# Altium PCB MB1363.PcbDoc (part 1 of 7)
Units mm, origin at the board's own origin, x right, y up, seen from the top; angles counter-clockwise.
Board outline 70 x 133.34 mm, 6 copper layers (Top Layer, Signal Layer 1, Signal Layer 2, Signal Layer 3, Signal Layer 4, Bottom Layer), stack 1.57 mm thick; 356 components, 294 nets, 1448 pads, 1107 vias.
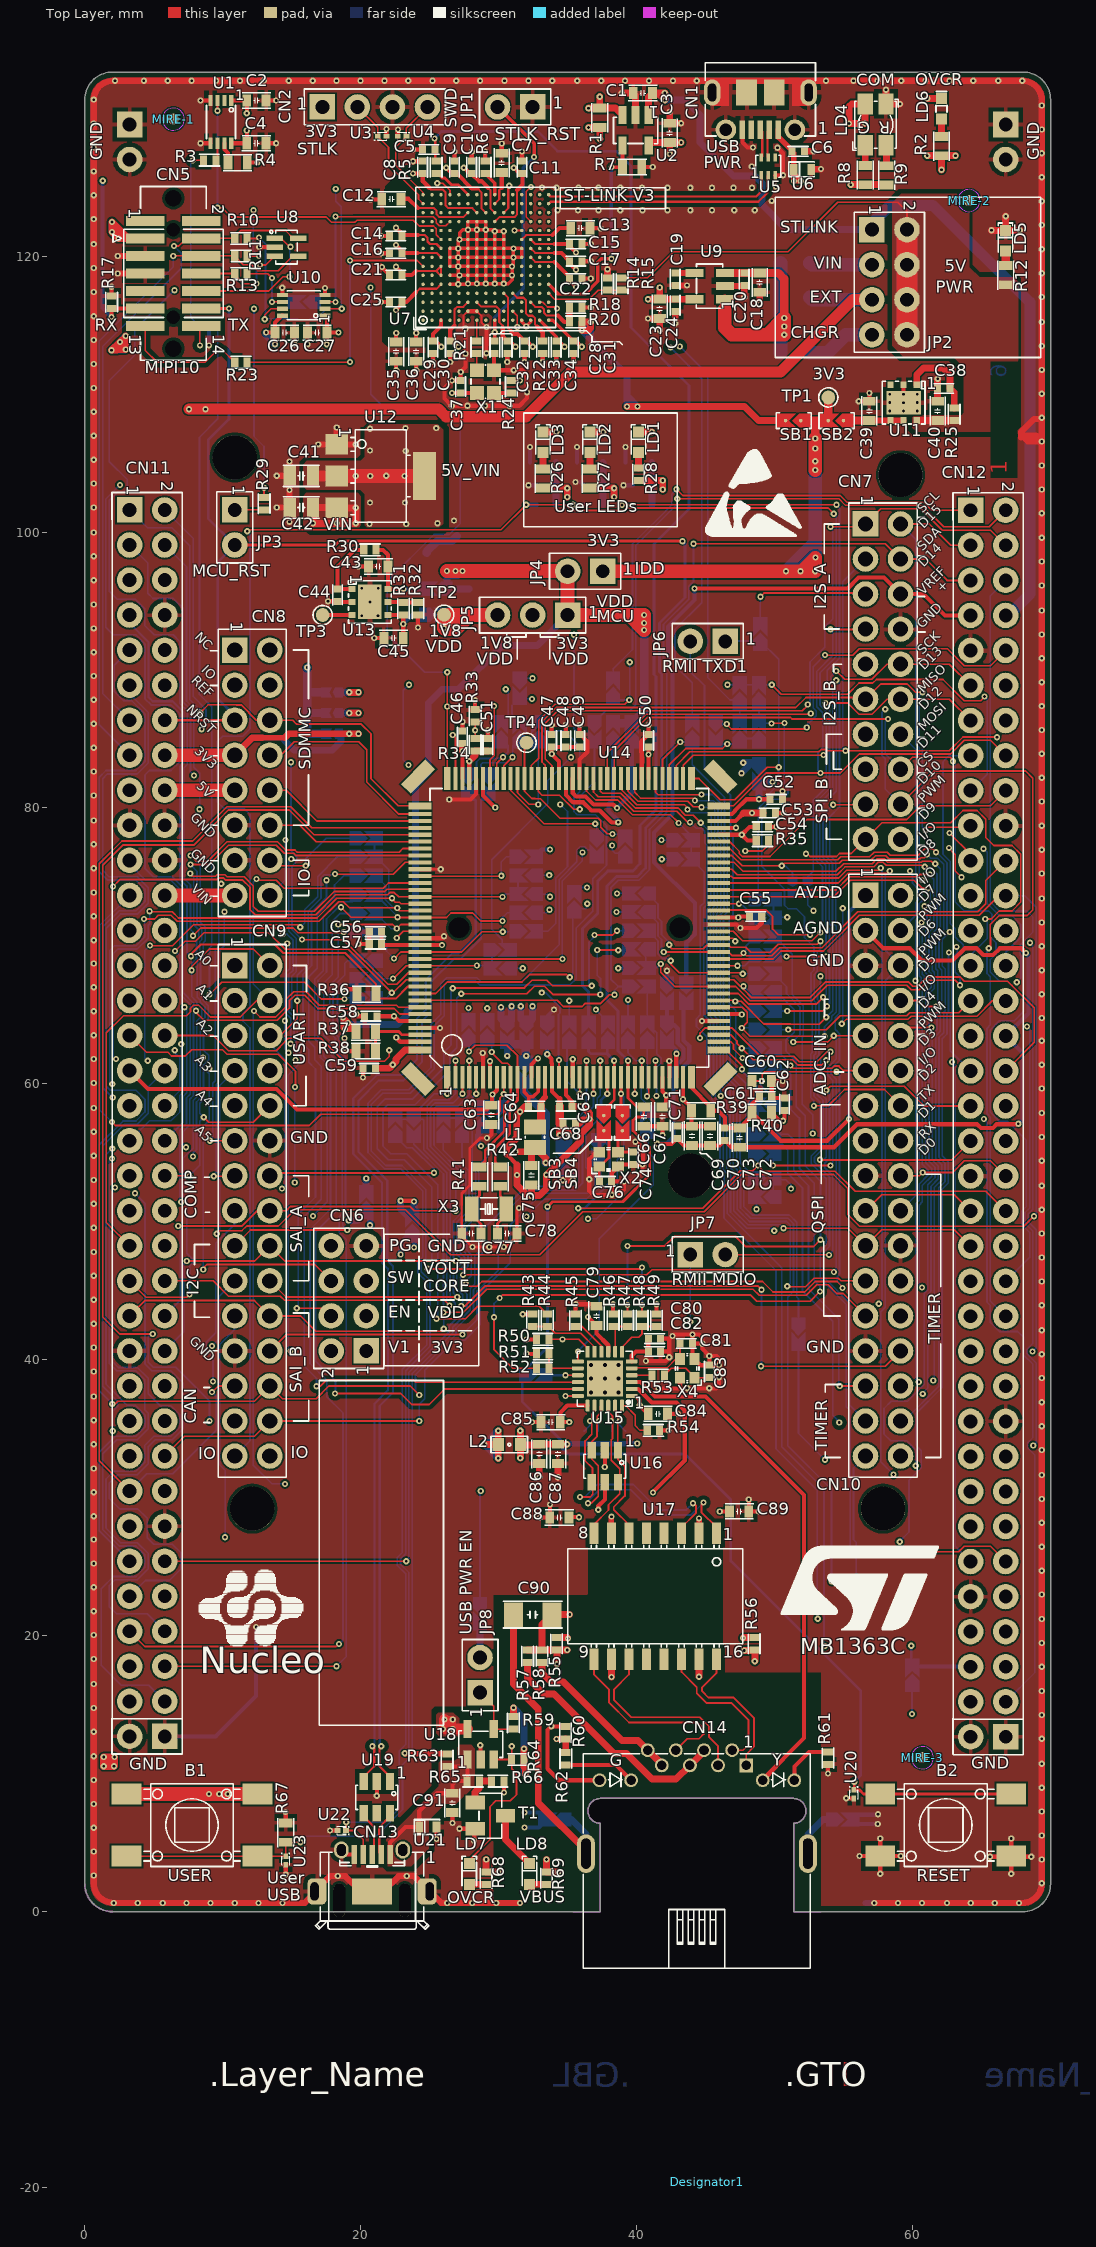
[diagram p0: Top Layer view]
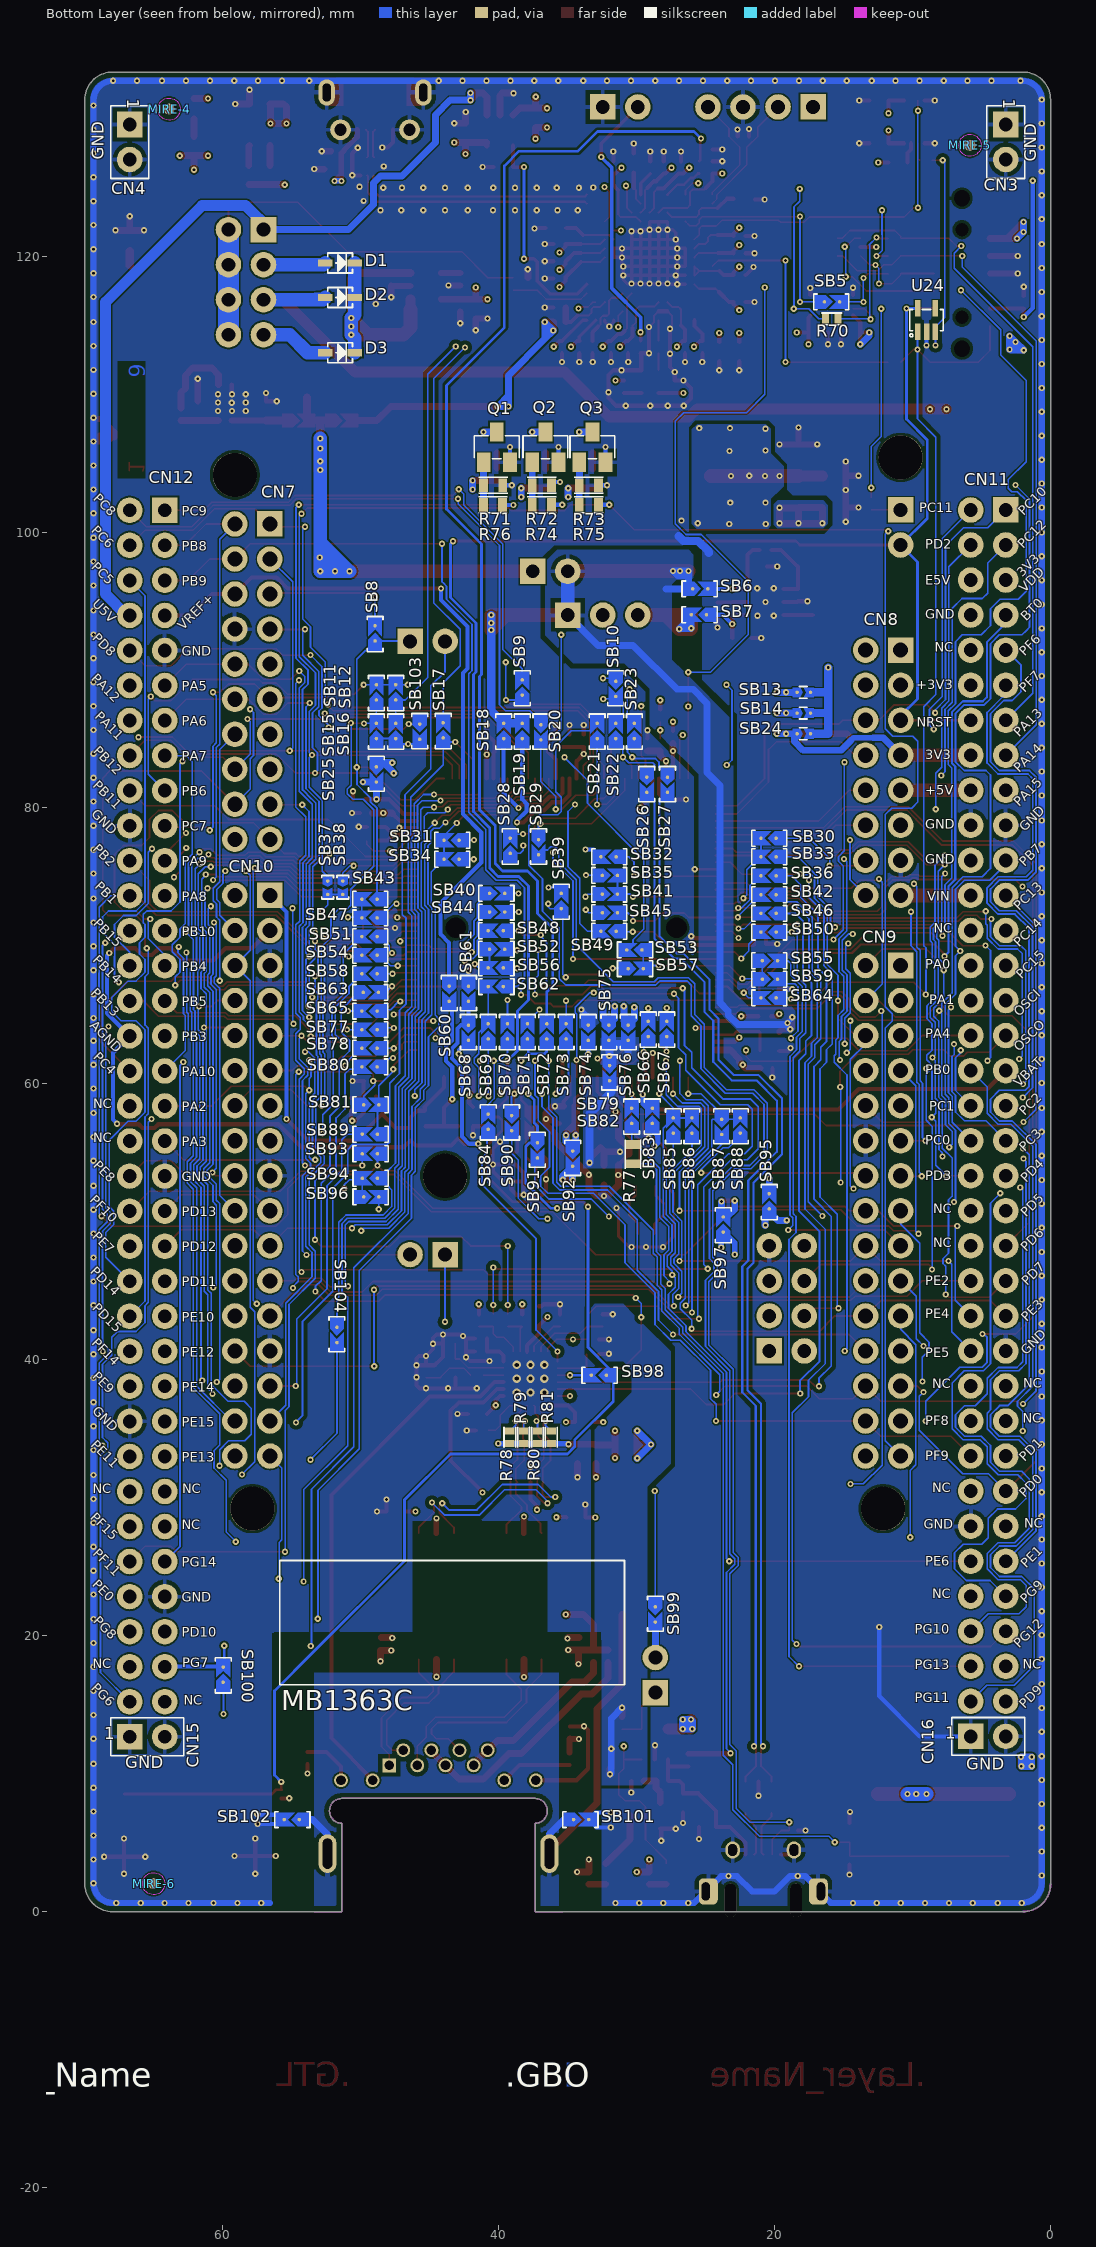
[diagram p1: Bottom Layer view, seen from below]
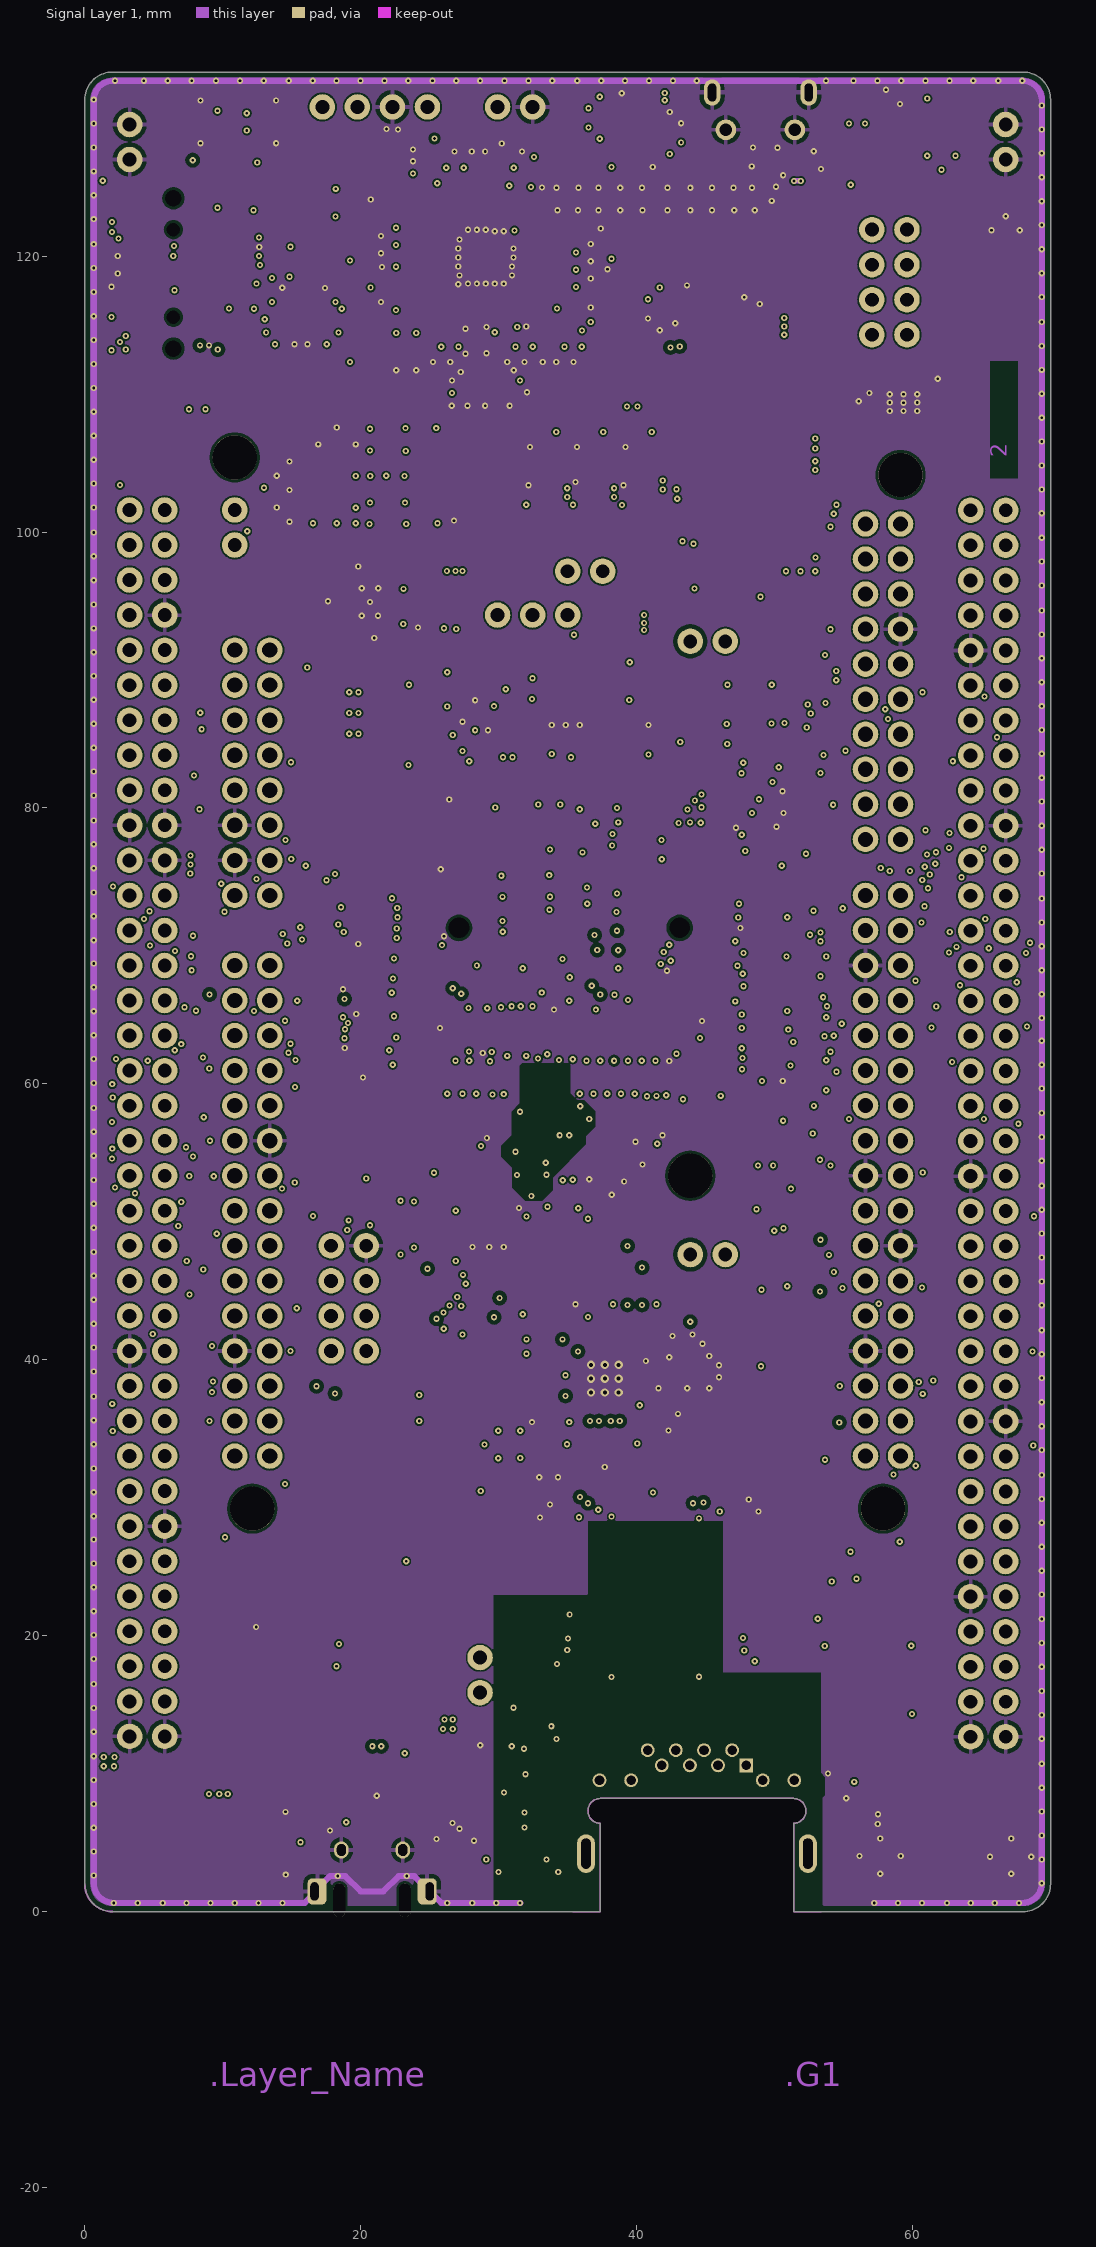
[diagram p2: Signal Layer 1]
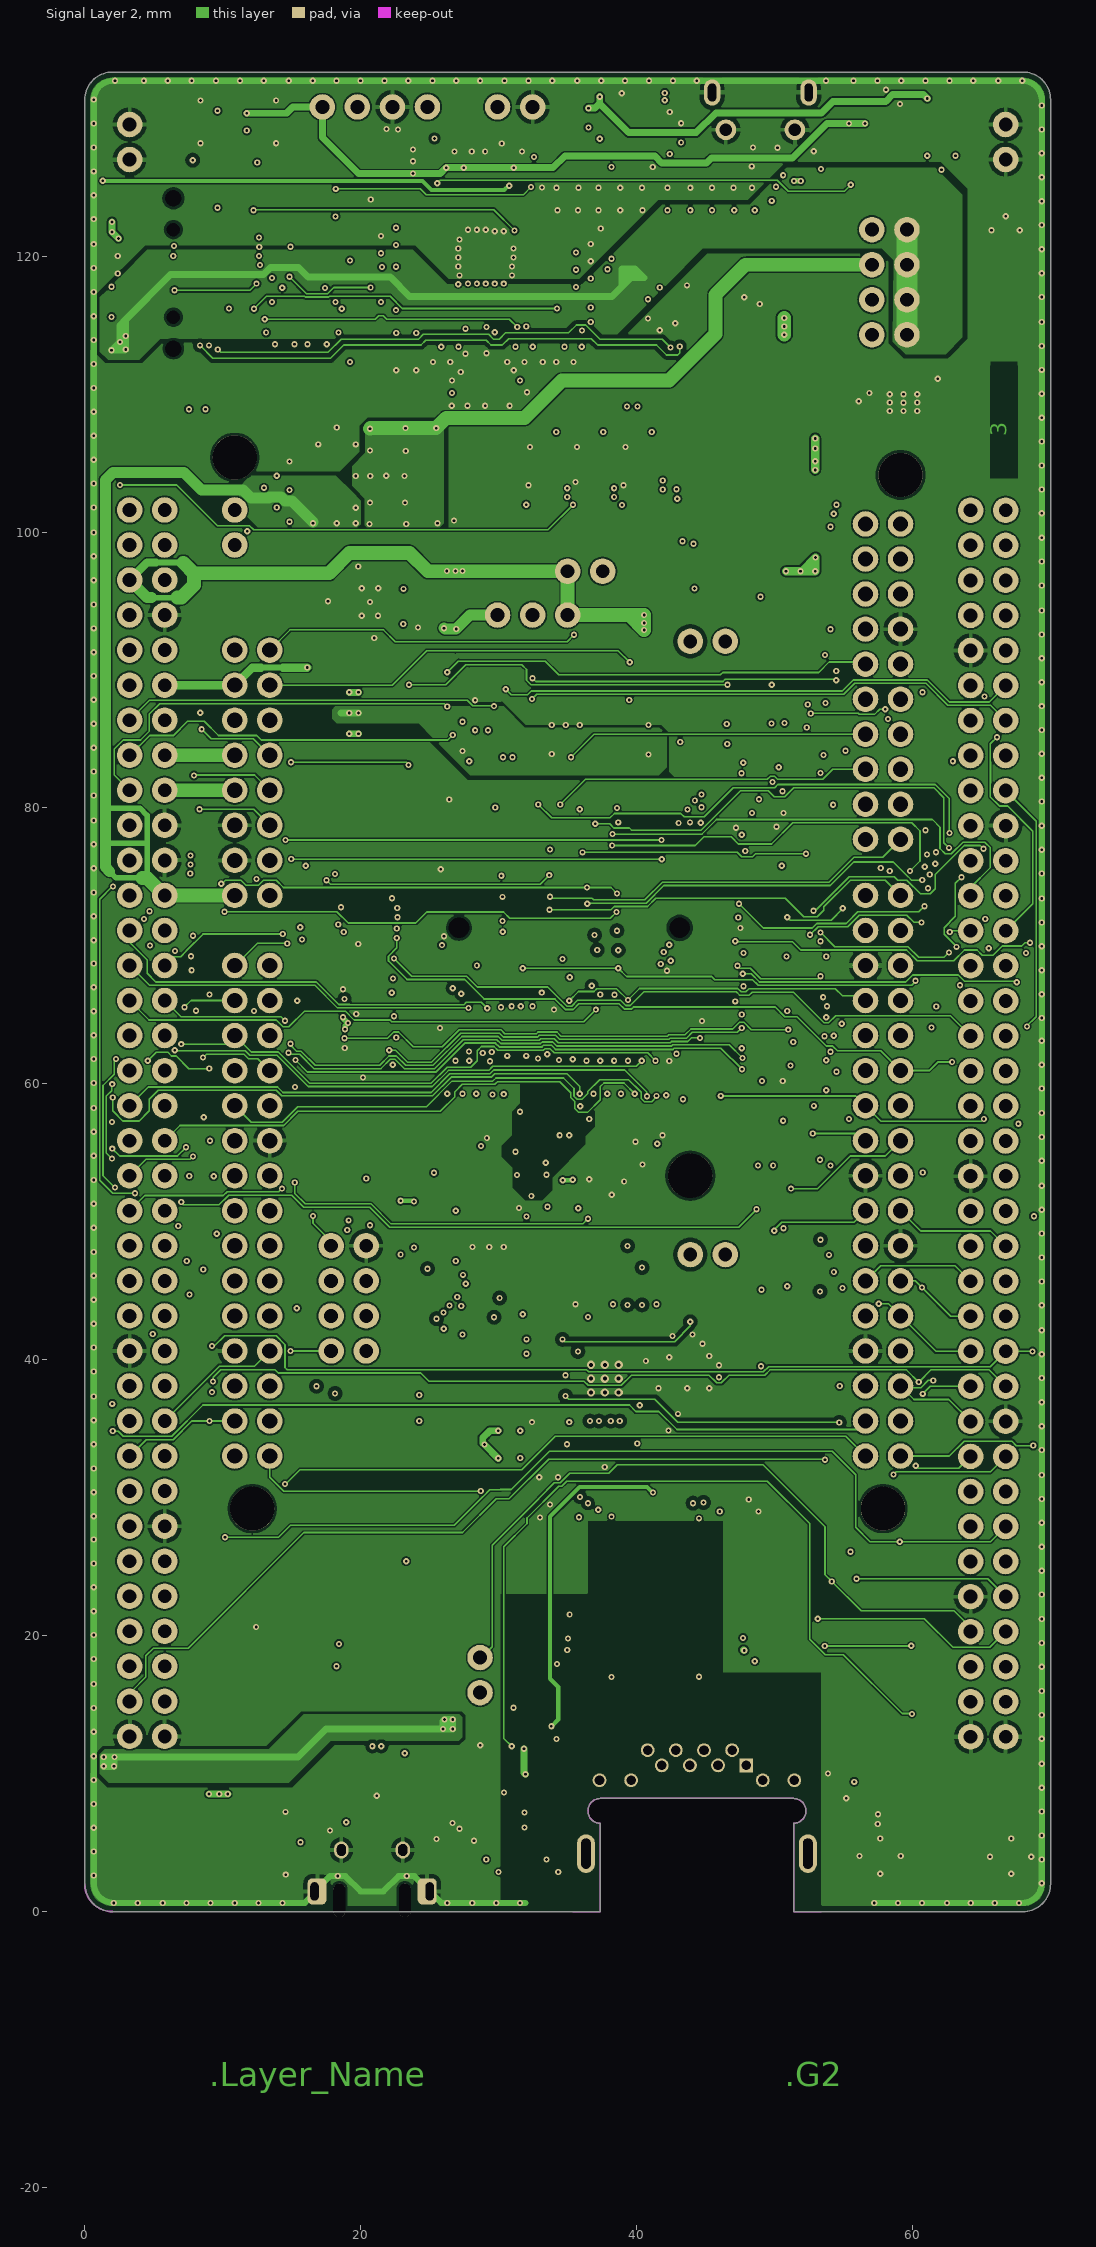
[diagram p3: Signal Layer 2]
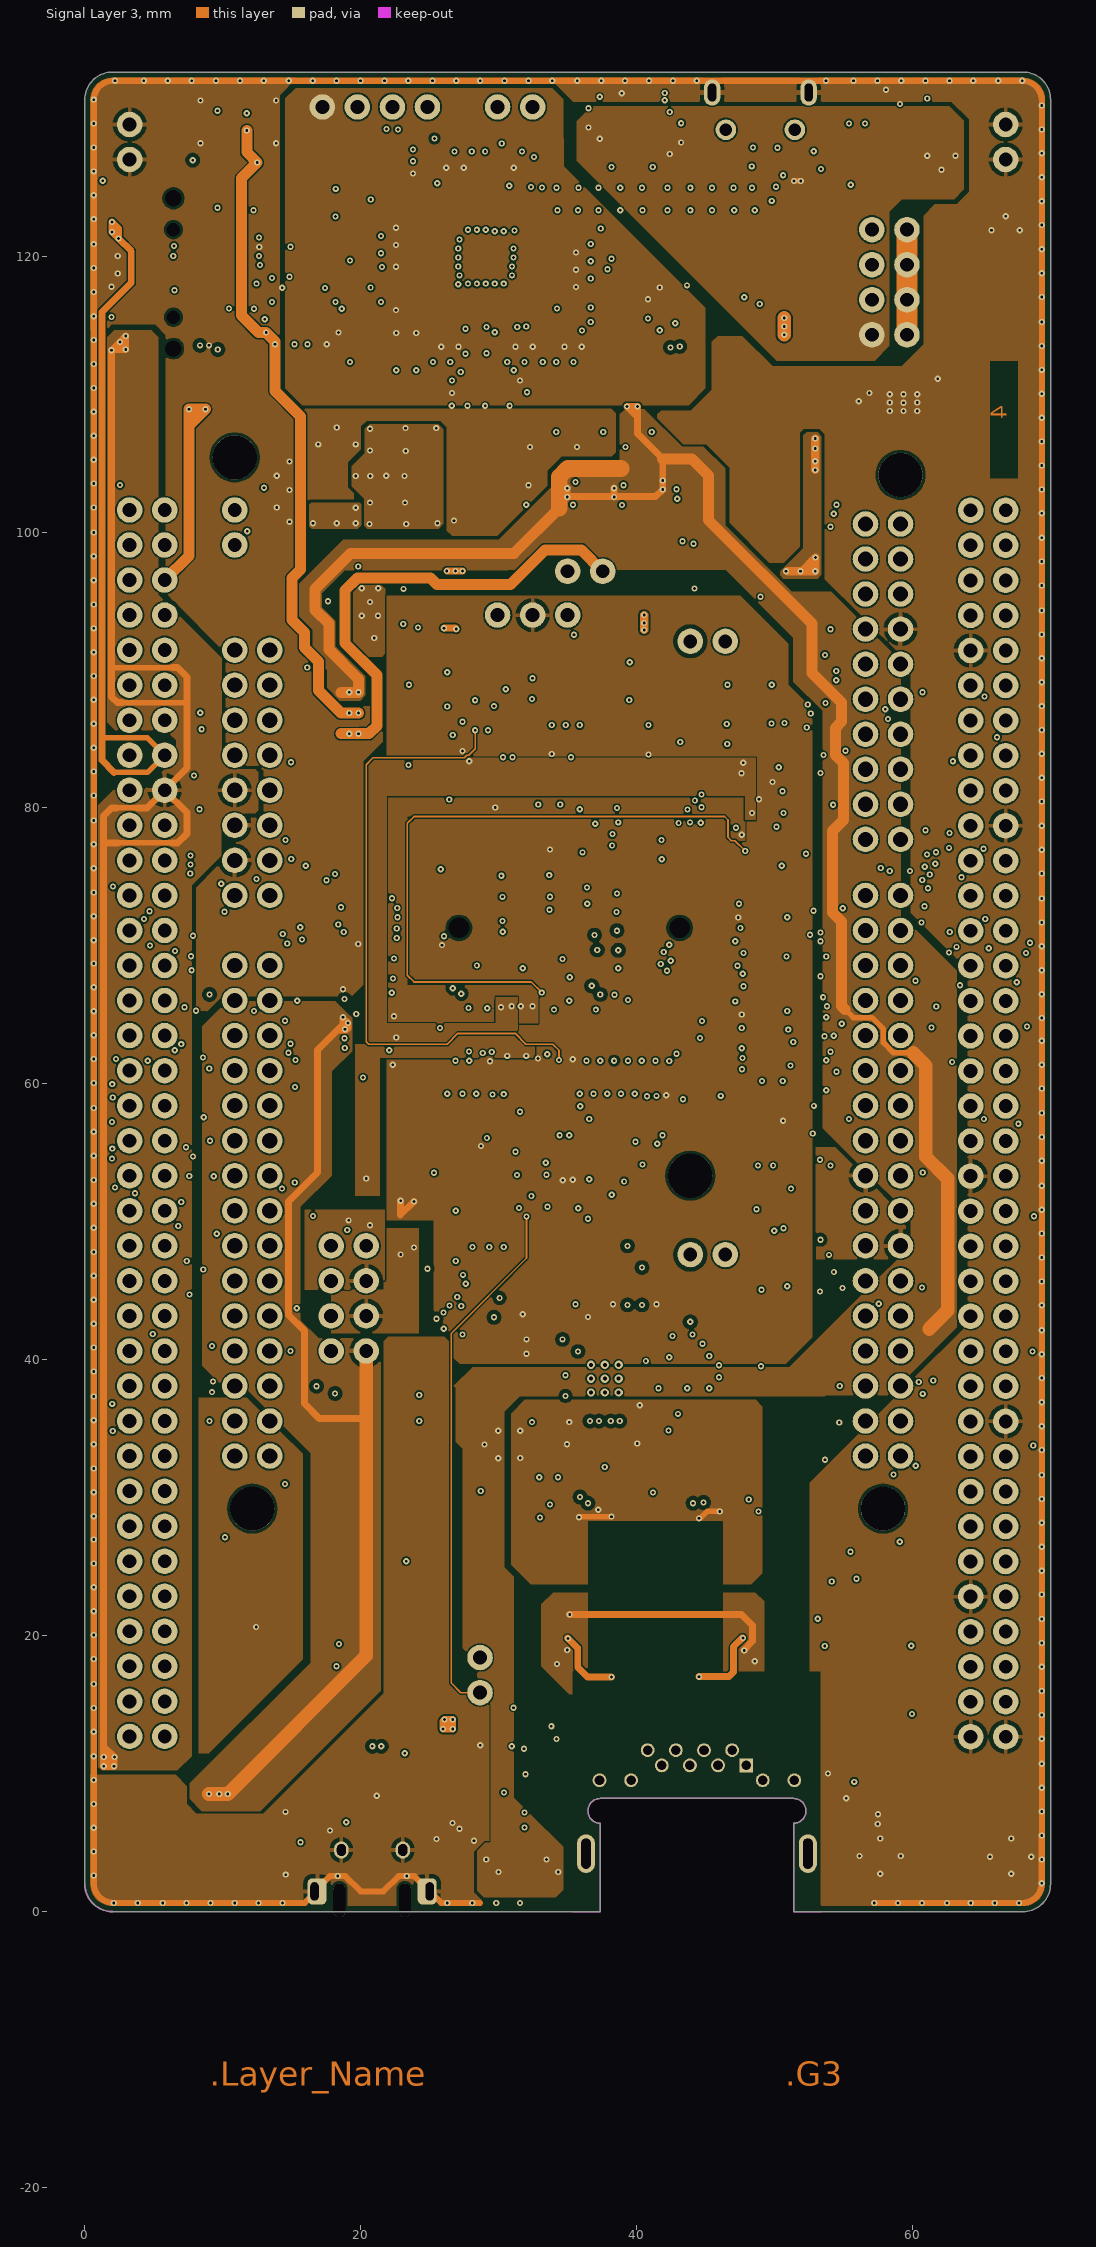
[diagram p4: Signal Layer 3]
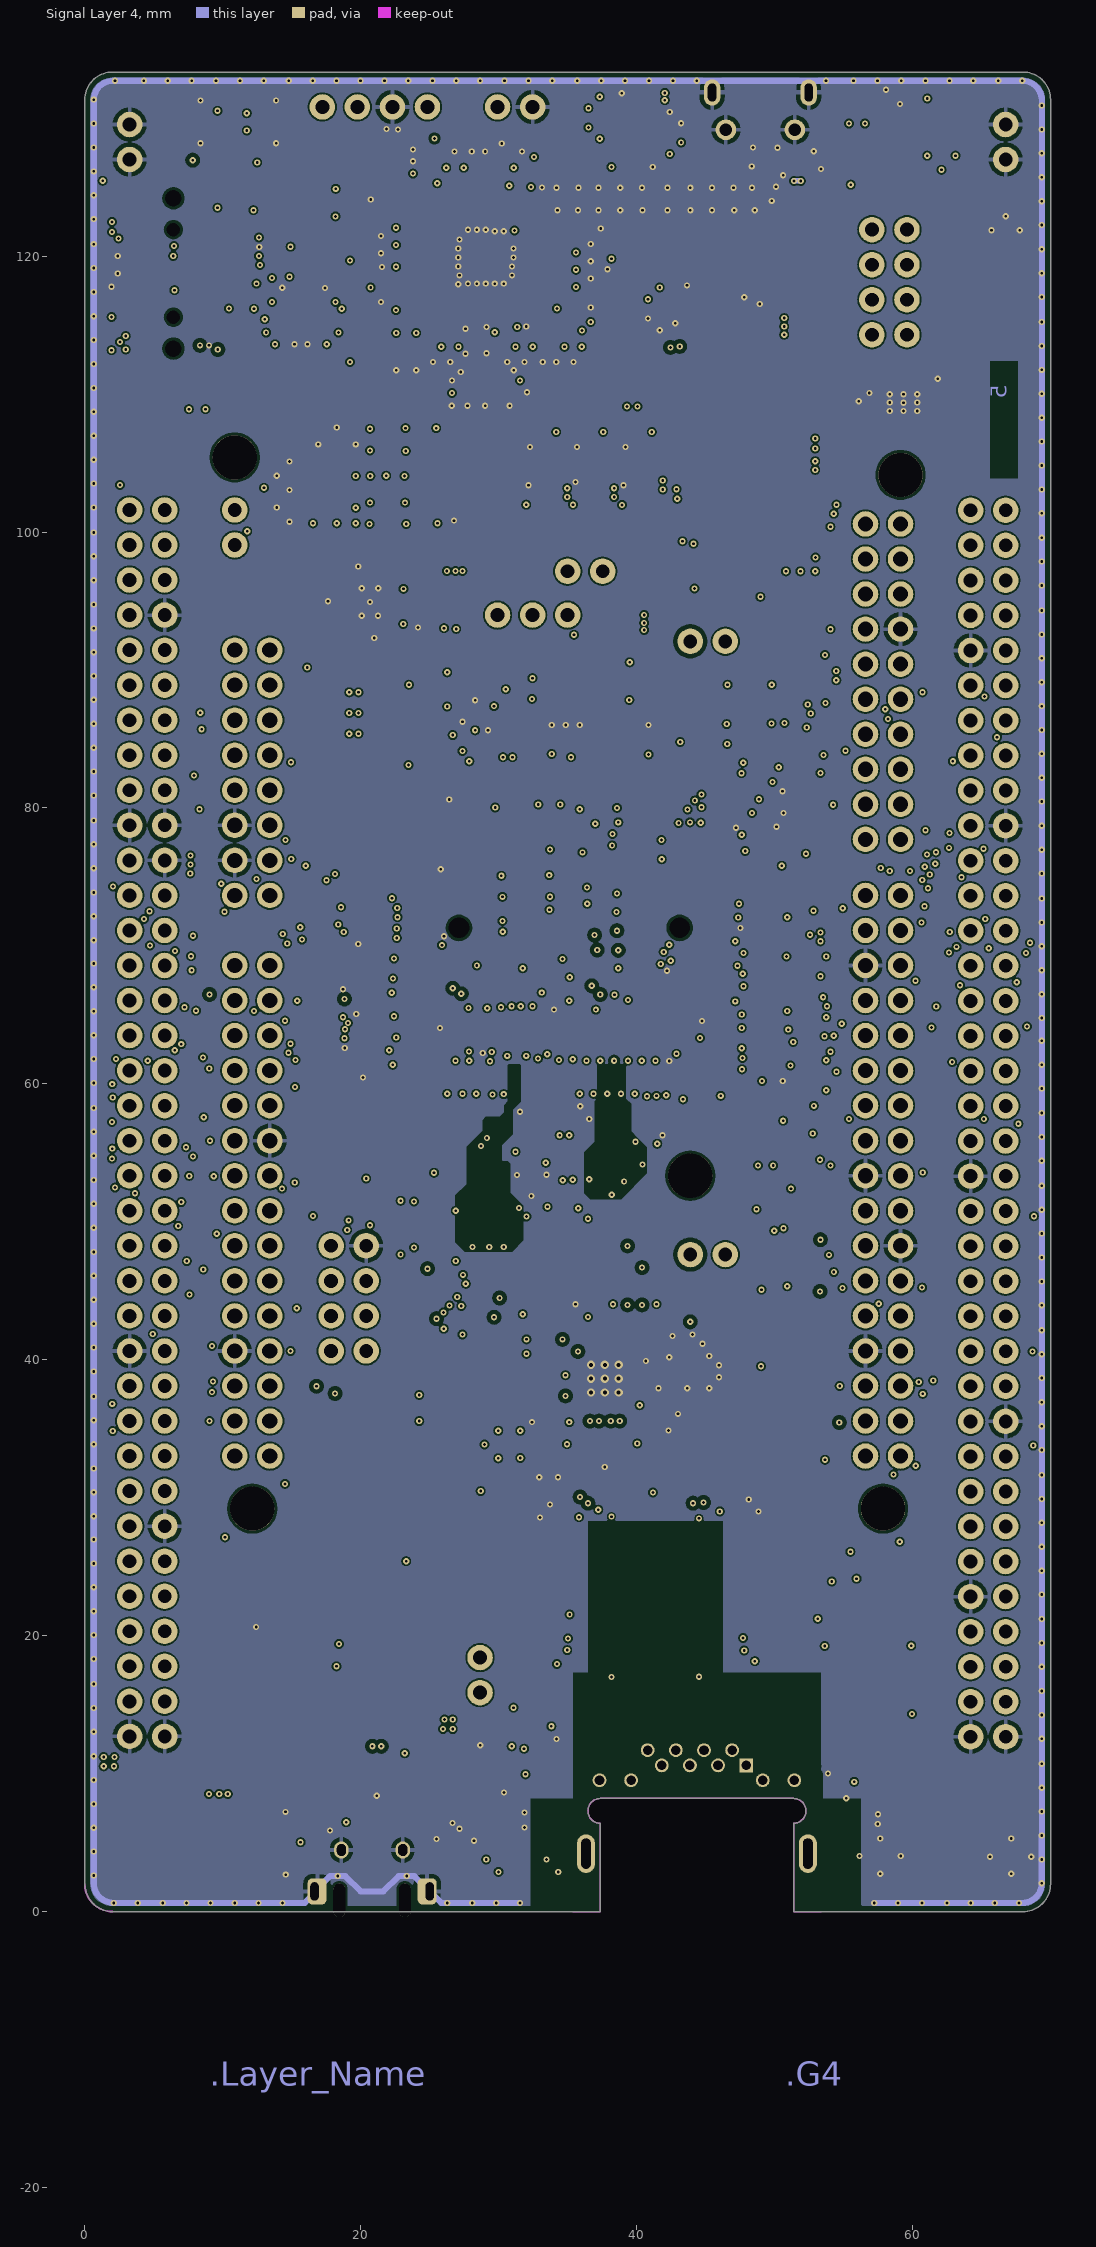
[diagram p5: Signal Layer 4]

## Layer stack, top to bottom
Top Solder: solder mask 0.015, Solder Resist, Dk 3.5
Top Layer: signal copper 0.042
Dielectric 1: prepreg 0.0991, FR-4, Dk 4.2
Signal Layer 1: signal copper 0.0348
Dielectric 2: core 0.1016, Dk 4.2
Signal Layer 2: signal copper 0.0348
Dielectric 3: prepreg 0.9457, Dk 4.2
Signal Layer 3: signal copper 0.0348
Dielectric 4: core 0.1016, Dk 4.2
Signal Layer 4: signal copper 0.0348
Dielectric 5: prepreg 0.0991, Dk 4.2
Bottom Layer: signal copper 0.042
Bottom Solder: solder mask 0.015, Solder Resist, Dk 3.5

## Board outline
0,2 ccw(c2,2) 2,0 37.369,0 37.369,6.4 cw(c37.369,7.3) 36.469,7.3 cw(c37.369,7.3) 37.369,8.2 51.369,8.2 cw(c51.369,7.3) 52.269,7.3 cw(c51.369,7.3) 51.369,6.4 51.369,0 68,0 ccw(c68,2) 70,2 70,131.34 ccw(c68,131.34) 68,133.34 2,133.34 ccw(c2,131.34) 0,131.34

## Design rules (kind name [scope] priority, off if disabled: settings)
BoardOutlineClearance [All] p1: gap=0.4 ignorepadtopadclearanceinfootprint=FALSE
Clearance Clearance_RMII_SINGLE_50R [InNetClass('NC_RMII_SINGLE_50R')] p1: gap=0.12 ignorepadtopadclearanceinfootprint=TRUE except(0.2: Arc-Hole Track-Hole SMDPad-SMDPad SMDPad-THPad SMDPad-Hole THPad-THPad THPad-Hole Via-Via Via-Hole Fill-Hole Poly-Hole Region-Hole Text-Hole; 0.3: Arc-Fill Arc-Poly Track-Track Track-Fill Track-Poly SMDPad-Fill SMDPad-Poly THPad-Fill THPad-Poly Via-Fill Via-Poly Fill-Fill Fill-Poly Poly-Poly)
Clearance Clearance_VCP_ISO300 [InNetClass('NC_VCP_ISO300')] p2: gap=0.12 ignorepadtopadclearanceinfootprint=TRUE except(0.2: Arc-Hole Track-Hole SMDPad-SMDPad SMDPad-THPad SMDPad-Hole THPad-THPad THPad-Hole Via-Via Via-Hole Fill-Hole Poly-Hole Region-Hole Text-Hole; 0.3: Arc-Fill Arc-Poly Track-Track Track-Fill Track-Poly SMDPad-Fill SMDPad-Poly THPad-Fill THPad-Poly Via-Fill Via-Poly Fill-Fill Fill-Poly Poly-Poly)
Clearance Clearance_USB_DIFF_90R [InNetClass('NC_USB_DIFF_90R')] p3: gap=0.12 ignorepadtopadclearanceinfootprint=TRUE except(0.2: Arc-Hole Track-Hole SMDPad-SMDPad SMDPad-THPad SMDPad-Hole THPad-THPad THPad-Hole Via-Via Via-Hole Fill-Hole Poly-Hole Region-Hole Text-Hole; 0.3: Arc-Fill Arc-Poly Track-Fill Track-Poly SMDPad-Fill SMDPad-Poly THPad-Fill THPad-Poly Via-Fill Via-Poly Fill-Fill Fill-Poly Poly-Poly)
Clearance Clearance_RXTX_DIFF_100R [InNetClass('NC_RXTX_DIFF_100R')] p4: gap=0.12 ignorepadtopadclearanceinfootprint=TRUE except(0.2: Arc-Hole Track-Hole SMDPad-SMDPad SMDPad-THPad SMDPad-Hole THPad-THPad THPad-Hole Via-Via Via-Hole Fill-Hole Poly-Hole Region-Hole Text-Hole; 0.3: Arc-Fill Arc-Poly Track-Fill Track-Poly SMDPad-Fill SMDPad-Poly THPad-Fill THPad-Poly Via-Fill Via-Poly Fill-Fill Fill-Poly Poly-Poly)
Clearance Clearance_STLK_ISO200 [InNetClass('NC_STLK_W200-ISO200')] p5: gap=0.12 ignorepadtopadclearanceinfootprint=TRUE except(0.2: Arc-Poly Arc-Hole Track-Track Track-Poly Track-Hole SMDPad-SMDPad SMDPad-THPad SMDPad-Poly SMDPad-Hole THPad-THPad THPad-Poly THPad-Hole Via-Via Via-Poly Via-Hole Fill-Poly Fill-Hole Poly-Poly Poly-Hole Region-Hole Text-Hole; 0.3: Arc-Fill Track-Fill SMDPad-Fill THPad-Fill Via-Fill Fill-Fill)
Clearance [All] p6: gap=0.12 ignorepadtopadclearanceinfootprint=TRUE except(0.2: Arc-Hole Track-Hole SMDPad-SMDPad SMDPad-THPad SMDPad-Hole THPad-THPad THPad-Hole Via-Via Via-Hole Fill-Hole Poly-Hole Region-Hole Text-Hole; 0.3: Arc-Fill Track-Fill SMDPad-Fill THPad-Fill Via-Fill Fill-Fill)
ComponentClearance [All] p1: gap=0 collisioncheckmode=3 verticalgap=0 showdistances=FALSE
DiffPairsRouting DiffPairsRouting_USB_90R [InDifferentialPairClass('DPC_USB_DIFF_90R')] p1: maxlimit=0.252 minlimit=0.226 mostfreqgap=0.226 toplayer_mingap=0.226 toplayer_maxgap=0.226 toplayer_minwidth=0.155 toplayer_maxwidth=0.155 toplayer_prefwidth=0.155 midlayer1_mingap=0.226 midlayer1_maxgap=0.226 midlayer1_minwidth=0.155 midlayer1_maxwidth=0.155 midlayer1_prefwidth=0.155 midlayer2_mingap=0.252 midlayer2_prefgap=0.252 midlayer2_minwidth=0.13 midlayer2_maxwidth=0.13 midlayer2_prefwidth=0.13 midlayer3_maxgap=0.226 midlayer3_prefgap=0.226 midlayer3_minwidth=0.155 midlayer3_maxwidth=0.155 midlayer3_prefwidth=0.155 midlayer4_mingap=0.226 midlayer4_maxgap=0.226 midlayer4_minwidth=0.155 midlayer4_maxwidth=0.155 midlayer4_prefwidth=0.155 bottomlayer_mingap=0.226 bottomlayer_maxgap=0.226 bottomlayer_minwidth=0.155 bottomlayer_maxwidth=0.155 bottomlayer_prefwidth=0.155 maxuncoupledlength=12.7
DiffPairsRouting DiffPairsRouting_RXTX_100R [InDifferentialPairClass('DPC_RXTX_DIFF_100R')] p2: maxlimit=0.277 minlimit=0.252 mostfreqgap=0.277 toplayer_maxgap=0.252 toplayer_prefgap=0.252 toplayer_minwidth=0.11 toplayer_maxwidth=0.13 toplayer_prefwidth=0.13 midlayer1_maxgap=0.252 midlayer1_prefgap=0.252 midlayer1_minwidth=0.13 midlayer1_maxwidth=0.13 midlayer1_prefwidth=0.13 midlayer2_mingap=0.277 midlayer2_minwidth=0.104 midlayer2_maxwidth=0.104 midlayer2_prefwidth=0.104 midlayer3_maxgap=0.252 midlayer3_prefgap=0.252 midlayer3_minwidth=0.13 midlayer3_maxwidth=0.13 midlayer3_prefwidth=0.13 midlayer4_maxgap=0.252 midlayer4_prefgap=0.252 midlayer4_minwidth=0.13 midlayer4_maxwidth=0.13 midlayer4_prefwidth=0.13 bottomlayer_maxgap=0.252 bottomlayer_prefgap=0.252 bottomlayer_minwidth=0.11 bottomlayer_maxwidth=0.13 bottomlayer_prefwidth=0.13 maxuncoupledlength=12.7
FabricationTestPointUsage TestPointUsage [All] p1: valid=0 allowmultiple=FALSE
FabricationTestpoint Testpoint [(IsPad And (OnTopLayer Or OnBottomLayer))] p1: side=3 testpointundercomponent=TRUE minsize=1.016 maxsize=2.54 preferedsize=1.524 minholesize=0 maxholesize=1.016 preferedholesize=0.813 testpointgrid=0.025 allowsidetop=TRUE allowsidebottom=TRUE usegrid=TRUE gridtolerance=0
HoleSize [All] p1: absolutevalues=TRUE maxlimit=3.81 minlimit=0.025 maxpercent=80.000 minpercent=20.000
MaxMinImpedance "Schematic Impedance Constraint_3" [InNet('USB_DEV_HS_P')] p1: minimum=85,00 maximum=95,00
MaxMinImpedance "Schematic Impedance Constraint_2" [InNet('USB_DEV_HS_N')] p2: minimum=85,00 maximum=95,00
MaxMinImpedance "Schematic Impedance Constraint_1" [InNet('USB_DEV_HS_CN_P')] p3: minimum=85,00 maximum=95,00
MaxMinImpedance "Schematic Impedance Constraint" [InNet('USB_DEV_HS_CN_N')] p4: minimum=85,00 maximum=95,00
MinimumSolderMaskSliver [All] p1: minsoldermaskwidth=0
PolygonConnect PolygonConnect_10 [All vs IsNamedPolygon('USB_FS_VBUS_L01_P068')] p1: connectstyle=Direct reliefconductorwidth=0.254 reliefentries=4 polygonreliefangle="90 Angle" airgapwidth=0.254
PolygonConnect PolygonConnect_9 [All vs IsNamedPolygon('5V_L03_P060')] p2: connectstyle=Direct reliefconductorwidth=0.254 reliefentries=4 polygonreliefangle="90 Angle" airgapwidth=0.254
PolygonConnect PolygonConnect_8 [All vs IsNamedPolygon('5V_L01_P058')] p3: connectstyle=Direct reliefconductorwidth=0.254 reliefentries=4 polygonreliefangle="90 Angle" airgapwidth=0.254
PolygonConnect PolygonConnect_7 [All vs IsNamedPolygon('3V3_STLK_L04_P044')] p4: connectstyle=Direct reliefconductorwidth=0.254 reliefentries=4 polygonreliefangle="90 Angle" airgapwidth=0.254
PolygonConnect PolygonConnect_6 [All vs IsNamedPolygon('5V_USB_CHGR_L04_P042')] p5: connectstyle=Direct reliefconductorwidth=0.254 reliefentries=4 polygonreliefangle="90 Angle" airgapwidth=0.254
PolygonConnect PolygonConnect_5 [All vs IsNamedPolygon('5V_L01_P038')] p6: connectstyle=Direct reliefconductorwidth=0.254 reliefentries=4 polygonreliefangle="90 Angle" airgapwidth=0.254
PolygonConnect PolygonConnect_4 [All vs IsNamedPolygon('5V_L01_P038')] p7: thpad.connectstyle=Relief thpad.reliefconductorwidth=0.4 thpad.reliefentries=4 thpad.polygonreliefangle="90 Angle" thpad.airgapwidth=0.4 smdpad.connectstyle=Direct smdpad.reliefconductorwidth=0.254 smdpad.reliefentries=4 smdpad.polygonreliefangle="90 Angle" smdpad.airgapwidth=0.254 via.connectstyle=Direct via.reliefconductorwidth=0.254 via.reliefentries=4 via.polygonreliefangle="90 Angle" via.airgapwidth=0.254
PolygonConnect PolygonConnect_3 [All vs IsNamedPolygon('5V_VIN_L01_P028')] p8: connectstyle=Direct reliefconductorwidth=0.254 reliefentries=4 polygonreliefangle="90 Angle" airgapwidth=0.254
PolygonConnect PolygonConnect_2 [All vs IsNamedPolygon('VIN_L01_P026')] p9: connectstyle=Direct reliefconductorwidth=0.254 reliefentries=4 polygonreliefangle="90 Angle" airgapwidth=0.254
PolygonConnect PolygonConnect_1 [All vs IsNamedPolygon('GND_L01_P024')] p10: connectstyle=Direct reliefconductorwidth=0.254 reliefentries=4 polygonreliefangle="90 Angle" airgapwidth=0.254
PolygonConnect [All] p11: thpad.connectstyle=Relief thpad.reliefconductorwidth=0.3 thpad.reliefentries=4 thpad.polygonreliefangle="90 Angle" thpad.airgapwidth=0.3 smdpad.connectstyle=Relief smdpad.reliefconductorwidth=0.3 smdpad.reliefentries=4 smdpad.polygonreliefangle="90 Angle" smdpad.airgapwidth=0.3 via.connectstyle=Direct via.reliefconductorwidth=0.254 via.reliefentries=4 via.polygonreliefangle="90 Angle" via.airgapwidth=0.254
RoutingLayers RoutingLayers_USB_DIFF_90R [InDifferentialPairClass('DPC_USB_DIFF_90R')] p1: top layer_v5=TRUE mid layer 1_v5=TRUE mid layer 2_v5=TRUE mid layer 3_v5=TRUE mid layer 4_v5=TRUE bottom layer_v5=TRUE
RoutingLayers RoutingLayers_RXTX_DIFF_100R [InDifferentialPairClass('DPC_RXTX_DIFF_100R')] p2: top layer_v5=TRUE mid layer 1_v5=TRUE mid layer 2_v5=TRUE mid layer 3_v5=TRUE mid layer 4_v5=TRUE bottom layer_v5=TRUE
RoutingLayers RoutingLayers_RMII_SINGLE_50R [InNetClass('NC_RMII_SINGLE_50R')] p3: top layer_v5=TRUE mid layer 1_v5=TRUE mid layer 2_v5=TRUE mid layer 3_v5=TRUE mid layer 4_v5=TRUE bottom layer_v5=TRUE
RoutingVias RoutingVias_Default [All] p1: holewidth=0.2 width=0.45 viastyle="Through Hole" minholewidth=0.2 minwidth=0.45 maxholewidth=0.2 maxwidth=0.45
SilkToSilkClearance [All] p1: silktosilkclearance=0.102
SilkToSolderMaskClearance SilkscreenOverComponentPads [IsPad] p1: minsilkscreentomaskgap=0.102 clearancetoexposedcopper=TRUE
SolderMaskExpansion [All] p1: expansion=0.102
Width Width_RMII_SINGLE_50R [InNetClass('NC_RMII_SINGLE_50R')] p1: maxlimit=0.127 minlimit=0.102 preferedwidth=0.127 toplayer_minwidth=0.127 midlayer1_minwidth=0.127 midlayer2_maxwidth=0.102 midlayer2_prefwidth=0.102 midlayer3_minwidth=0.127 midlayer4_minwidth=0.127 bottomlayer_minwidth=0.127 minimp=50.000000 maximp=50.000000 favimp=50.000000
Width Width_POWER_300u [InNetClass('NC_POWER_300u')] p2: maxlimit=10 minlimit=0.12 preferedwidth=0.3 minimp=50.000000 maximp=50.000000 favimp=50.000000
Width Width_GROUND [InNetClass('NC_GROUND')] p3: maxlimit=10 minlimit=0.12 preferedwidth=0.3 minimp=50.000000 maximp=50.000000 favimp=50.000000
Width Width_POWER_500u [InNetClass('NC_POWER_500u')] p4: maxlimit=10 minlimit=0.12 preferedwidth=0.5 minimp=50.000000 maximp=50.000000 favimp=50.000000
Width Width_POWER_SMPS [InNetClass('NC_POWER_SMPS')] p5: maxlimit=10 minlimit=0.12 preferedwidth=0.5 minimp=50.000000 maximp=50.000000 favimp=50.000000
Width Width_STLK_W200 [InNetClass('NC_STLK_W200-ISO200')] p6: maxlimit=10 minlimit=0.2 preferedwidth=0.2 minimp=50.000000 maximp=50.000000 favimp=50.000000
Width [All] p7: maxlimit=10 minlimit=0.12 preferedwidth=0.12 minimp=50.000000 maximp=50.000000 favimp=50.000000
Width Width_RD_N [InNet('RD_N')] p8: maxlimit=10 minlimit=0.11 preferedwidth=0.12 toplayer_maxwidth=0.11 toplayer_prefwidth=0.11 midlayer1_minwidth=0.12 midlayer2_minwidth=0.12 midlayer3_minwidth=0.12 midlayer4_minwidth=0.12 bottomlayer_maxwidth=0.11 bottomlayer_prefwidth=0.11 minimp=50.000000 maximp=50.000000 favimp=50.000000
Width Width_TD_P [InNet('TD_P')] p9: maxlimit=10 minlimit=0.11 preferedwidth=0.12 toplayer_maxwidth=0.11 toplayer_prefwidth=0.11 midlayer1_minwidth=0.12 midlayer2_minwidth=0.12 midlayer3_minwidth=0.12 midlayer4_minwidth=0.12 bottomlayer_maxwidth=0.11 bottomlayer_prefwidth=0.11 minimp=50.000000 maximp=50.000000 favimp=50.000000
21 further rules are at their usual default settings.

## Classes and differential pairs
net class NC_STLK_W200-ISO200: NetR5_1 PH0 STLK_MCO
net class NC_VCP_ISO300: T_VCP_RX T_VCP_TX
net class NC_RMII_SINGLE_50R: RMII_CRS_DV RMII_MDC RMII_MDIO RMII_REF_CLK RMII_RXD0 RMII_RXD1 RMII_TX_EN RMII_TXD0 RMII_TXD1
net class NC_USB_DIFF_90R: USB_DEV_HS_CN_N USB_DEV_HS_CN_P USB_DEV_HS_N USB_DEV_HS_P USB_FS_CN_N USB_FS_CN_P USB_FS_N USB_FS_P
differential pair class DPC_RXTX_DIFF_100R: RD RX TD TX
differential pair class DPC_USB_DIFF_90R: USB_DEV_HS USB_DEV_HS_CN USB_FS USB_FS_CN
net class NC_RXTX_DIFF_100R: RD_N RD_P RX_N RX_P TD_N TD_P TX_N TX_P
net class NC_GROUND: AGND GND
net class NC_POWER_300u: VBAT VDDA VREFP
net class NC_POWER_SMPS: 1V2_MCU 1V2_VOUTCORE VCAP VDD_LDO VDD_MCU VDD_SMPS_IN VDD_SMPS_IND_OUT VDD_SMPS_OUT VOUTVDD
net class NC_POWER_500u: 1V8_VDD 3V3 3V3_PER 3V3_STLK 3V3_VDD 5V 5V_EXT 5V_USB_CHGR 5V_USB_STLK 5V_VIN IOREF USB_FS_VBUS VIN
differential pair USB_FS_CN: +USB_FS_CN_P -USB_FS_CN_N
differential pair RD: +RD_P -RD_N
differential pair RX: +RX_P -RX_N
differential pair TD: +TD_P -TD_N
differential pair TX: +TX_P -TX_N
differential pair USB_DEV_HS_CN: +USB_DEV_HS_CN_P -USB_DEV_HS_CN_N
differential pair USB_DEV_HS: +USB_DEV_HS_P -USB_DEV_HS_N
differential pair USB_FS: +USB_FS_P -USB_FS_N

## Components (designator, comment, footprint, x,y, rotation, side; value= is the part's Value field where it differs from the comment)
B1 "SW-PUSH-CMS_BLUE" SWI_WEALTHMETAL_TD-0341_4P_BLUE 7.767,6.273 r270 top locked value=SW_BLUE
B2 "SW-PUSH-CMS_BLACK" SWI_WEALTHMETAL_TD-0341_4P_BLACK 62.403,6.273 r270 top locked value=SW_BLACK
C1 "Capacitor" C0603 40.448,131.82 r0 top value=1uF
C2 "Capacitor" C0603 12.441,131.279 r180 top value=100nF
C3 "Capacitor" C0603 42.396,128.927 r270 top value=1uF
C4 "Capacitor" C0603 12.441,128.179 r0 top value=100nF
C5 "Capacitor" C0402 24.941,127.729 r0 top value=20pF
C6 "Capacitor" C0402 51.699,127.593 r180 top value=100pF
C7 "Capacitor" C0603 30.216,126.754 r270 top value=2.2uF
C8 "Capacitor" C0402 24.491,126.429 r270 top value=100nF
C9 "Capacitor" C0402 26.791,126.429 r270 top value=100nF
C10 "Capacitor" C0402 28.041,126.429 r270 top value=100nF
C11 "Capacitor" C0402 31.691,126.429 r270 top value=100nF
C12 "Capacitor" C0603 22.225,124.125 r0 top value=2.2uF
C13 "Capacitor" C0603 35.925,122.025 r180 top value=2.2uF
C14 "Capacitor" C0402 22.541,121.454 r0 top value=100nF
C15 "Capacitor" C0402 35.591,120.879 r180 top value=100nF
C16 "Capacitor" C0402 22.541,120.204 r0 top value=100nF
C17 "Capacitor" C0402 35.591,119.629 r180 top value=100nF
C18 "Capacitor" C0603 48.916,118.079 r270 top value=1uF
C19 "Capacitor" C0402 42.791,118.329 r90 top value=10nF
C20 "Capacitor" C0402 47.794,118.32 r90 top value=100nF
C21 "Capacitor" C0402 22.541,118.629 r0 top value=100nF
C22 "Capacitor" C0402 35.591,118.379 r180 top value=100nF
C23 "Capacitor" C0603 41.666,116.179 r90 top value=1uF
C24 "Capacitor" C0402 42.791,116.429 r90 top value=100nF
C25 "Capacitor" C0402 22.541,116.679 r0 top value=100nF
C26 "Capacitor" C0603 14.491,114.454 r0 top value=100nF
C27 "Capacitor" C0603 16.841,114.454 r0 top value=100nF
C28 "Capacitor" C0402 29.716,113.404 r90 top value=100nF
C29 "Capacitor" C0402 25.241,113.404 r90 top value=100nF
C30 "Capacitor" C0402 26.491,113.404 r90 top value=100nF
C31 "Capacitor" C0402 30.616,113.404 r90 top value=100nF
C32 "Capacitor" C0402 31.866,113.404 r90 top value=100nF
C33 "Capacitor" C0402 34.166,113.404 r90 top value=100nF
C34 "Capacitor" C0402 35.416,113.404 r90 top value=100nF
C35 "Capacitor" C0603 22.566,113.079 r90 top value=4.7uF
C36 "Capacitor" C0603 24.016,113.079 r90 top value=1uF
C37 "Capacitor" C0402 27.241,110.529 r270 top value=100nF
C38 "Capacitor" C0402 62.266,110.404 r180 top value=100nF
C39 "Capacitor" C0603 56.866,108.779 r270 top value=4.7uF
C40 "Capacitor" C0603 61.816,108.779 r270 top value=4.7uF
C41 "Capacitor" C0805 15.691,104.074 r0 top value=10uF
C42 "Capacitor" C0805 15.691,101.774 r0 top value=10uF
C43 "Capacitor" C0603 21.266,97.504 r180 top value=4.7uF
C44 "Capacitor" C0402 18.316,95.429 r270 top value=100nF
C45 "Capacitor" C0603 22.375,92.325 r0 top value=4.7uF
C46 "Capacitor" C0402 27.366,85.129 r270 top value=100nF
C47 "Capacitor" C0402 33.839,84.879 r270 top value=100nF
C48 "Capacitor" C0402 34.866,84.879 r270 top value=100nF
C49 "Capacitor" C0402 35.866,84.879 r270 top value=100nF
C50 "Capacitor" C0402 40.866,84.879 r270 top value=100nF
C51 "Capacitor" C0402 29.216,84.579 r90 top value=100nF
C52 "Capacitor" C0402 50.116,80.629 r180 top value=100nF
C53 "Capacitor" C0402 49.616,79.629 r0 top value=100nF
C54 "Capacitor" C0402 49.116,78.629 r180 top value=100nF
C55 "Capacitor" C0402 48.616,72.129 r180 top value=100nF
C56 "Capacitor" C0402 21.066,71.029 r0 top value=100nF
C57 "Capacitor" C0402 21.066,70.129 r0 top value=100nF
C58 "Capacitor" C0402 20.716,64.904 r0 top value=100nF
C59 "Capacitor" C0402 20.616,61.129 r0 top value=100nF
C60 "Capacitor" C0603 49.066,60.204 r180 top value=100nF
C61 "Capacitor" C0402 49.341,59.079 r0 top value=100nF
C62 "Capacitor" C0402 50.716,58.529 r90 top value=100nF
C63 "Capacitor" C0603 29.466,57.754 r90 top value=1uF
C64 "Capacitor" C0402 32.616,58.379 r0 top value=220pF
C65 "Capacitor" C0402 34.866,58.379 r180 top value=10uF
C66 "Capacitor" C0603 40.516,57.629 r90 top value=100nF
C67 "Capacitor" C0603 41.866,57.629 r90 top value=4.7uF
C68 "Capacitor" C0402 35.116,57.129 r180 top value=10uF
C69 "Capacitor" C0603 44.016,56.229 r270 top value=1uF
C70 "Capacitor" C0603 45.316,56.229 r90 top value=100nF
C71 "Capacitor" C0402 42.941,56.479 r90 top value=100nF
C72 "Capacitor" C0603 47.466,56.104 r270 top value=1uF
C73 "Capacitor" C0402 46.391,56.354 r90 top value=100nF
C74 "Capacitor" C0402 39.766,54.604 r270 top value=5.6pF
C75 "Capacitor" C0603 32.366,53.379 r90 top value=10uF
C76 "Capacitor" C0402 37.741,52.929 r0 top value=5.6pF
C77 "Capacitor" C0603 28.016,49.154 r180 top value=5.1pF
C78 "Capacitor" C0603 30.616,49.154 r0 top value=5.1pF
C79 "Capacitor" C0603 37.091,43.179 r270 top value=100nF
C80 "Capacitor" C0402 41.291,41.529 r180 top value=1uF
C81 "Capacitor" C0402 43.591,41.179 r180 top value=5.6pF
C82 "Capacitor" C0402 41.291,40.604 r180 top value=470pF
C83 "Capacitor" C0402 45.266,39.154 r270 top value=5.6pF
C84 "Capacitor" C0603 41.541,36.079 r180 top value=100nF
C85 "Capacitor" C0603 33.766,35.479 r180 top value=100nF
C86 "Capacitor" C0603 32.941,33.179 r90 top value=100nF
C87 "Capacitor" C0603 34.291,33.179 r90 top value=10uF
C88 "Capacitor" C0603 34.396,28.566 r0 top value=100nF
C89 "Capacitor" C0603 47.429,29.009 r180 top value=100nF
C90 "Capacitor" C1206_H1P6 32.466,21.529 r0 top value=1nF
C91 "Capacitor" C0603 26.641,7.879 r90 top value=4.7uF
CN1 "USB_uB_105017.0001" CON_USBMICROB_MOLEX_105017-0001_H2P90 48.966,133.308 r180 top locked value=USB_uB_105017-0001
CN2 "Header 4x1" CON_SAMTEC_TSW-104-07-G-S 21.026,130.809 r0 top
CN3 "Jumper_Header 2x1" CON_SAMTEC_TSW-102-09-X-S 3.246,128.269 r270 bottom locked value="Header 2x1 16mm"
CN4 "Jumper_Header 2x1" CON_SAMTEC_TSW-102-09-X-S 66.746,128.269 r270 bottom locked value="Header 2x1 16mm"
CN5 "Header 7x2" CON_STDC14_Receiver_MEDIUM_WITH_MIPI10_3D 6.421,118.744 r270 top value="MIPI10 on STDC14 footprint"
CN6 "Jumper_Header 4x2" CON_SAMTEC_TSW-104-07-X-D 19.121,44.449 r90 top value=Jumper_Header_4x2
CN7 "Socket 10x2_N144_ARD" CON_SAMTEC_SSW-110-23-X-D_N144_ARD 57.856,89.153 r90 top locked
CN8 "Socket 8x2_N144_ARD" CON_SAMTEC_SSW-108-23-X-D_N144_ARD 12.136,82.549 r90 top locked
CN9 "Socket 15x2_N144_ARD" CON_SAMTEC_SSW-115-23-X-D_N144_ARD 12.136,50.799 r90 top locked
CN10 "Socket 17x2_N144_ARD" CON_SAMTEC_SSW-117-23-X-D_N144_ARD 57.856,53.339 r90 top locked
CN11 "Header 35x2" CON_SAMTEC_TSW-135-07-X-D 4.516,58.419 r270 top locked
CN12 "Header 35x2" CON_SAMTEC_TSW-135-07-X-D 65.476,58.394 r270 top locked
CN13 "USB_uAB_47590.0001" CON_USBMICROAB_MOLEX_47590-0001_H3 20.823,0.014 r0 top locked value="USB uAB ZX62RD-AB-5P8(30)"
CN14 "RJ45_KRJ-CB4.2GYZNL" CON_RJ45_DGKYD_KRJ-CB4.2GYZNL 44.369,0 r0 top locked value=KRJ-CB4.2GYZNL
CN15 "Jumper_Header 2x1" CON_SAMTEC_TSW-102-09-X-S 65.476,12.674 r180 bottom locked value="Header 2x1 16mm"
CN16 "Jumper_Header 2x1" CON_SAMTEC_TSW-102-09-X-S 4.516,12.699 r180 bottom value="Header 2x1 16mm"
D1 "BAT60JFILM" DIO_SOD323 51.5,119.5 r180 bottom
D2 "BAT60JFILM" DIO_SOD323 51.5,117 r180 bottom
D3 "BAT60JFILM" DIO_SOD323 51.5,113 r180 bottom
Designator1 "Comment" Sheetbox_6L2S 0.04,-24.86 r0 top
JP1 "Jumper_Header 2x1" CON_SAMTEC_TSW-102-07-G-S 31.186,130.809 r180 top value="Shunt not fitted"
JP2 "Jumper_Header 4x2 Fitted 1-2" CON_SAMTEC_TSW-104-07-X-D 58.32,118.109 r270 top locked value="Shunt Fitted 1-2"
JP3 "Jumper_Header 2x1 Fitted" CON_SAMTEC_TSW-102-07-G-S 10.866,100.329 r270 top value="Shunt Fitted"
JP4 "Jumper_Header 2x1 Fitted" CON_SAMTEC_TSW-102-07-G-S 36.266,97.154 r180 top value="Shunt Fitted"
JP5 "Jumper_Header 3x1 Fitted 1-2" CON_SAMTEC_TSW-103-07-F-S 32.456,93.979 r180 top value="Shunt Fitted 1-2"
JP6 "Jumper_Header 2x1 Fitted" CON_SAMTEC_TSW-102-07-G-S 45.156,92.074 r180 top value="Shunt Fitted"
JP7 "Jumper_Header 2x1 Fitted" CON_SAMTEC_TSW-102-07-G-S 45.156,47.624 r0 top value="Shunt Fitted"
JP8 "Jumper_Header 2x1 Fitted" CON_SAMTEC_TSW-102-07-G-S 28.646,17.144 r90 top value="Shunt Fitted"
L1 "Inductor" L0805_H0P9 32.616,56.129 r270 top value="2.2uH, 1.2A"
L2 "BEAD" L0603 30.766,33.854 r180 top value=600R@100MHz
LD1 "LED_green" LED_0603_OSRAM_LG-Q396-PS-35_GREEN_1A2K_H0P4 40.141,106.497 r90 top locked value=GREEN
LD2 "LED_yellow" LED_0603_OSRAM_LY-Q396-P1Q2-36_YELLOW_1A2K_H0P4 36.616,106.497 r90 top value=YELLOW
LD3 "LED_red" LED_0603_OSRAM_LS-Q976-NR-1_RED_1A2K_H0P8 33.208,106.497 r90 top value=RED
LD4 "LD_BICOLOR_CMS" LED_BI-GR_HSMF-A201-A00J1 57.316,129.529 r180 top
LD5 "LED_green" LED_0603_OSRAM_LG-Q396-PS-35_GREEN_1A2K_H0P4 66.746,121.119 r90 top value=GREEN
LD6 "LED_red" LED_0603_RED 62.091,130.679 r90 top value=RED
LD7 "LED_red" LED_0603_VISHAY_VLMS1300-GS08_RED_1A2K_H0P8 27.866,2.729 r90 top value=RED
LD8 "LED_green" LED_0603_OSRAM_LG-Q396-PS-35_GREEN_1A2K_H0P4 32.241,2.729 r90 top value=GREEN
MIRE-1 "Comment" MIRE_PLACE_SMD_0P8MM 6.416,129.929 r0 top
MIRE-2 "Comment" MIRE_PLACE_SMD_0P8MM 64.091,124.029 r0 top
MIRE-3 "Comment" MIRE_PLACE_SMD_0P8MM 60.716,11.154 r0 top
MIRE-4 "Comment" MIRE_PLACE_SMD_0P8MM 63.891,130.654 r180 bottom
MIRE-5 "Comment" MIRE_PLACE_SMD_0P8MM 5.841,128.029 r180 bottom
MIRE-6 "Comment" MIRE_PLACE_SMD_0P8MM 65.016,2.029 r180 bottom
Q1 "9013-SOT23" NPN_SOT23 40.141,106.147 r180 bottom
Q2 "9013-SOT23" NPN_SOT23 36.616,106.147 r180 bottom
Q3 "9013-SOT23" NPN_SOT23 33.208,106.147 r180 bottom
R1 "Resistor" R0603 37.325,130.029 r270 top value=100K
R2 "Resistor" R0603 62.091,127.979 r270 top value=1K
R3 "Resistor" R0402 9.041,126.954 r0 top value=47R
R4 "Resistor" R0603 11.066,126.779 r0 top value=100K
R5 "Resistor" R0402 25.466,126.429 r90 top value=100R
R6 "Resistor" R0402 29.016,126.429 r270 top value=3K
R7 "Resistor" R0603 39.673,126.459 r0 top value=10K
R8 "Resistor" R0603 56.566,125.877 r270 top value=330R
R9 "Resistor" R0603 58.116,125.852 r270 top value=330R
R10 "Resistor" R0402 11.316,121.279 r0 top value=47R
R11 "Resistor" R0402 11.316,120.004 r180 top value=47R
R12 "Resistor" R0603 66.746,118.619 r270 top value=620R
R13 "Resistor" R0402 11.316,118.729 r0 top value=47R
R14 "Resistor" R0402 37.891,117.979 r270 top value=4K7
R15 "Resistor" R0402 38.941,117.979 r270 top value=2K7
R17 "Resistor" R0402 1.941,116.654 r270 top value=100R
R18 "Resistor" R0402 35.591,116.279 r0 top value=4K7
R20 "Resistor" R0402 35.591,115.229 r0 top value=4K7
R21 "Resistor" R0402 28.416,113.404 r90 top value=100R
R22 "Resistor" R0402 33.191,113.404 r90 top value=10K
R23 "Resistor" R0402 11.316,112.304 r180 top value=47R
R24 "Resistor" R0402 30.916,110.529 r270 top value=10K
R25 "Resistor" R0402 63.016,108.529 r270 top value=10K
R26 "Resistor" R0603 33.216,103.879 r270 top value=360R
R27 "Resistor" R0603 36.616,103.879 r270 top value=470R
R28 "Resistor" R0402 40.141,104.179 r270 top value=270R
R29 "Resistor" R0402 12.991,102.054 r270 top value=47R
R30 "Resistor" R0402 20.666,98.704 r180 top value=10K
R31 "Resistor" R0402 23.1,94.45 r90 top value=27K
R32 "Resistor" R0402 24.15,94.45 r90 top value=56K
R33 "Resistor" R0402 28.291,86.679 r90 top value=0R
R34 "Resistor" R0402 28.291,84.579 r90 top value=0R
R35 "Resistor" R0402 49.116,77.629 r0 top value=0R
R36 "Resistor" R0603 20.416,66.504 r180 top value=10K
R37 "Resistor" R0603 20.366,63.753 r180 top value=10K
R38 "Resistor" R0603 20.366,62.379 r180 top value=10K
R39 "Resistor" R0603 44.666,58.054 r180 top value=0R
R40 "Resistor" R0603 49.066,57.929 r180 top value=0R
R41 "Resistor" R0603 28.616,53.279 r270 top value=0R
R42 "Resistor" R0603 30.116,53.279 r270 top value=0R
R43 "Resistor" R0402 32.466,42.854 r90 top value=10K
R44 "Resistor" R0402 33.516,42.854 r270 top value=33R
R45 "Resistor" R0402 35.566,42.854 r90 top value=10K
R46 "Resistor" R0402 38.291,42.854 r90 top value=10K
R47 "Resistor" R0402 39.341,42.854 r270 top value=33R
R48 "Resistor" R0402 40.391,42.854 r270 top value=33R
R49 "Resistor" R0402 41.441,42.854 r90 top value=10K
R50 "Resistor" R0402 33.191,41.479 r180 top value=1K5
R51 "Resistor" R0402 33.191,40.429 r180 top value=10K
R52 "Resistor" R0402 33.191,39.379 r0 top value=33R
R53 "Resistor" R0402 41.566,38.879 r180 top value=0R
R54 "Resistor" R0402 41.216,34.879 r0 top value=12K1
R55 "Resistor" R0402 34.191,19.404 r90 top value=75R
R56 "Resistor" R0402 48.516,19.404 r90 top value=75R
R57 "Resistor" R0402 32.091,18.504 r270 top value=75R
R58 "Resistor" R0402 33.141,18.504 r270 top value=75R
R59 "Resistor" R0402 31.066,13.679 r90 top value=47K
R60 "Resistor" R0402 34.841,12.973 r90 top value=10K
R61 "Resistor" R0402 53.866,11.129 r90 top value=270R
R62 "Resistor" R0402 34.866,11.079 r270 top value=270R
R63 "Resistor" R0402 26.266,10.979 r90 top value=10K
R64 "Resistor" R0402 31.391,11.024 r0 top value=47K
R65 "Resistor" R0402 28.141,9.454 r0 top value=47K
R66 "Resistor" R0402 29.941,9.454 r180 top value=10K
R67 "Resistor" R0603 14.566,5.729 r270 top value=100K
R68 "Resistor" R0402 29.091,2.429 r90 top value=360R
R69 "Resistor" R0402 33.466,2.429 r90 top value=270R
R70 "Resistor" R0402 15.866,115.454 r0 bottom value=100R
R71 "Resistor" R0603 40.411,103.385 r0 bottom value=100K
R72 "Resistor" R0603 36.866,103.379 r0 bottom value=100K
R73 "Resistor" R0603 33.466,103.379 r0 bottom value=100K
R74 "Resistor" R0603 36.866,101.979 r0 bottom value=47K
R75 "Resistor" R0603 33.466,101.979 r0 bottom value=47K
R76 "Resistor" R0603 40.414,101.967 r0 bottom value=47K
R77 "Resistor" R0603 30.266,54.904 r270 bottom value=330R
R78 "Resistor" R0402 39.191,34.379 r270 bottom value=49.9R
R79 "Resistor" R0402 38.191,34.379 r270 bottom value=49.9R
R80 "Resistor" R0402 37.191,34.379 r270 bottom value=49.9R
R81 "Resistor" R0402 36.191,34.379 r270 bottom value=49.9R
SB1 "SB_ON" SOLDER-BRIDGE_R0603-0R 51.391,108.079 r180 top
SB2 "SB_ON" SOLDER-BRIDGE_R0603-0R 54.491,108.079 r180 top
SB3 "SB_ON" SOLDER-BRIDGE_R0603-0R 37.616,57.204 r270 top
SB4 "SB_ON" SOLDER-BRIDGE_R0603-0R 38.966,57.204 r270 top
SB5 "SB_ON" SOLDER-BRIDGE_R0603-0R 15.891,116.679 r180 bottom
SB6 "SB_ON" SOLDER-BRIDGE_R0603-0R 25.441,95.879 r180 bottom
SB7 "SB_ON" SOLDER-BRIDGE_R0603-0R 25.441,94.004 r0 bottom
SB8 "SB_ON" SOLDER-BRIDGE_R0603-0R 48.966,92.604 r90 bottom
SB9 "SB_ON" SOLDER-BRIDGE_R0603-0R 38.291,88.679 r90 bottom
SB10 "SB_ON" SOLDER-BRIDGE_R0603-0R 31.516,88.679 r270 bottom
SB11 "SB_ON" SOLDER-BRIDGE_R0603-0R 48.866,88.329 r90 bottom
SB12 "SB_ON" SOLDER-BRIDGE_R0603-0R 47.466,88.329 r90 bottom
SB13 "SB_ON" SOLDER-BRIDGE_R0402-0R 17.925,88.375 r180 bottom
SB14 "SB_ON" SOLDER-BRIDGE_R0402-0R 17.925,86.875 r180 bottom
SB15 "SB_ON" SOLDER-BRIDGE_R0603-0R 48.866,85.529 r90 bottom
SB16 "SB_ON" SOLDER-BRIDGE_R0603-0R 47.466,85.529 r90 bottom
SB17 "SB_ON" SOLDER-BRIDGE_R0603-0R 44.025,85.575 r90 bottom
SB18 "SB_ON" SOLDER-BRIDGE_R0603-0R 39.641,85.529 r90 bottom
SB19 "SB_ON" SOLDER-BRIDGE_R0603-0R 38.291,85.529 r90 bottom
SB20 "SB_ON" SOLDER-BRIDGE_R0603-0R 36.941,85.529 r270 bottom
SB21 "SB_ON" SOLDER-BRIDGE_R0603-0R 32.866,85.529 r90 bottom
SB22 "SB_ON" SOLDER-BRIDGE_R0603-0R 31.516,85.529 r90 bottom
SB23 "SB_ON" SOLDER-BRIDGE_R0603-0R 30.166,85.529 r90 bottom
SB24 "SB_ON" SOLDER-BRIDGE_R0402-0R 17.925,85.375 r180 bottom
SB25 "SB_ON" SOLDER-BRIDGE_R0603-0R 48.866,82.479 r270 bottom
SB26 "SB_ON" SOLDER-BRIDGE_R0603-0R 29.266,81.729 r270 bottom
SB27 "SB_ON" SOLDER-BRIDGE_R0603-0R 27.766,81.729 r270 bottom
SB28 "SB_ON" SOLDER-BRIDGE_R0603-0R 39.166,77.204 r90 bottom
SB29 "SB_ON" SOLDER-BRIDGE_R0603-0R 37.116,77.204 r270 bottom
SB30 "SB_ON" SOLDER-BRIDGE_R0603-0R 20.391,77.804 r0 bottom
SB31 "SB_ON" SOLDER-BRIDGE_R0603-0R 43.366,77.654 r0 bottom
SB32 "SB_ON" SOLDER-BRIDGE_R0603-0R 31.991,76.454 r0 bottom
SB33 "SB_ON" SOLDER-BRIDGE_R0603-0R 20.391,76.454 r0 bottom
SB34 "SB_ON" SOLDER-BRIDGE_R0603-0R 43.366,76.279 r0 bottom
SB35 "SB_ON" SOLDER-BRIDGE_R0603-0R 31.991,75.104 r180 bottom
SB36 "SB_ON" SOLDER-BRIDGE_R0603-0R 20.391,75.079 r0 bottom
SB37 "SB_ON" SOLDER-BRIDGE_R0402-0R 52.4,74.25 r270 bottom
SB38 "SB_ON" SOLDER-BRIDGE_R0402-0R 51.3,74.25 r270 bottom
SB39 "SB_ON" SOLDER-BRIDGE_R0603-0R 35.466,73.204 r90 bottom
SB40 "SB_ON" SOLDER-BRIDGE_R0603-0R 40.166,73.804 r180 bottom
SB41 "SB_ON" SOLDER-BRIDGE_R0603-0R 31.991,73.754 r180 bottom
SB42 "SB_ON" SOLDER-BRIDGE_R0603-0R 20.391,73.704 r0 bottom
SB43 "SB_ON" SOLDER-BRIDGE_R0603-0R 49.316,73.379 r0 bottom
SB44 "SB_ON" SOLDER-BRIDGE_R0603-0R 40.166,72.454 r180 bottom
SB45 "SB_ON" SOLDER-BRIDGE_R0603-0R 31.991,72.404 r180 bottom
SB46 "SB_ON" SOLDER-BRIDGE_R0603-0R 20.391,72.354 r0 bottom
SB47 "SB_ON" SOLDER-BRIDGE_R0603-0R 49.316,72.029 r0 bottom
SB48 "SB_ON" SOLDER-BRIDGE_R0603-0R 40.166,71.104 r0 bottom
SB49 "SB_ON" SOLDER-BRIDGE_R0603-0R 31.991,71.054 r0 bottom
SB50 "SB_ON" SOLDER-BRIDGE_R0603-0R 20.391,71.004 r0 bottom
SB51 "SB_ON" SOLDER-BRIDGE_R0603-0R 49.316,70.679 r0 bottom
SB52 "SB_ON" SOLDER-BRIDGE_R0603-0R 40.166,69.754 r180 bottom
SB53 "SB_ON" SOLDER-BRIDGE_R0603-0R 30.116,69.704 r0 bottom
SB54 "SB_ON" SOLDER-BRIDGE_R0603-0R 49.316,69.329 r0 bottom
SB55 "SB_ON" SOLDER-BRIDGE_R0603-0R 20.391,68.929 r180 bottom
SB56 "SB_ON" SOLDER-BRIDGE_R0603-0R 40.166,68.404 r0 bottom
SB57 "SB_ON" SOLDER-BRIDGE_R0603-0R 30.116,68.354 r180 bottom
SB58 "SB_ON" SOLDER-BRIDGE_R0603-0R 49.316,67.979 r0 bottom
SB59 "SB_ON" SOLDER-BRIDGE_R0603-0R 20.391,67.579 r180 bottom
SB60 "SB_ON" SOLDER-BRIDGE_R0603-0R 43.591,66.579 r270 bottom
SB61 "SB_ON" SOLDER-BRIDGE_R0603-0R 42.191,66.579 r270 bottom
SB62 "SB_ON" SOLDER-BRIDGE_R0603-0R 40.166,67.054 r0 bottom
SB63 "SB_ON" SOLDER-BRIDGE_R0603-0R 49.316,66.629 r180 bottom
SB64 "SB_ON" SOLDER-BRIDGE_R0603-0R 20.391,66.229 r0 bottom
SB65 "SB_ON" SOLDER-BRIDGE_R0603-0R 49.316,65.279 r0 bottom
SB66 "SB_ON" SOLDER-BRIDGE_R0603-0R 29.166,63.929 r90 bottom
SB67 "SB_ON" SOLDER-BRIDGE_R0603-0R 27.816,63.929 r90 bottom
SB68 "SB_ON" SOLDER-BRIDGE_R0603-0R 42.191,63.754 r270 bottom
SB69 "SB_ON" SOLDER-BRIDGE_R0603-0R 40.766,63.754 r90 bottom
SB70 "SB_ON" SOLDER-BRIDGE_R0603-0R 39.366,63.754 r90 bottom
SB71 "SB_ON" SOLDER-BRIDGE_R0603-0R 37.916,63.754 r90 bottom
SB72 "SB_ON" SOLDER-BRIDGE_R0603-0R 36.516,63.754 r90 bottom
SB73 "SB_ON" SOLDER-BRIDGE_R0603-0R 35.116,63.754 r90 bottom
SB74 "SB_ON" SOLDER-BRIDGE_R0603-0R 33.509,63.753 r270 bottom
SB75 "SB_ON" SOLDER-BRIDGE_R0603-0R 32.015,63.753 r270 bottom
SB76 "SB_ON" SOLDER-BRIDGE_R0603-0R 30.616,63.753 r270 bottom
SB77 "SB_ON" SOLDER-BRIDGE_R0603-0R 49.316,63.929 r0 bottom
SB78 "SB_ON" SOLDER-BRIDGE_R0603-0R 49.316,62.579 r0 bottom
SB79 "SB_ON" SOLDER-BRIDGE_R0603-0R 31.966,60.829 r270 bottom
SB80 "SB_ON" SOLDER-BRIDGE_R0603-0R 49.316,61.229 r0 bottom
SB81 "SB_ON" SOLDER-BRIDGE_R0603-0R 49.291,58.479 r180 bottom
SB82 "SB_ON" SOLDER-BRIDGE_R0603-0R 30.366,57.629 r90 bottom
SB83 "SB_ON" SOLDER-BRIDGE_R0603-0R 28.866,57.629 r90 bottom
SB84 "SB_ON" SOLDER-BRIDGE_R0603-0R 40.766,57.204 r90 bottom
SB85 "SB_ON" SOLDER-BRIDGE_R0603-0R 27.341,56.929 r90 bottom
SB86 "SB_ON" SOLDER-BRIDGE_R0603-0R 25.991,56.929 r90 bottom
SB87 "SB_ON" SOLDER-BRIDGE_R0603-0R 23.841,56.929 r270 bottom
SB88 "SB_ON" SOLDER-BRIDGE_R0603-0R 22.491,56.929 r90 bottom
SB89 "SB_ON" SOLDER-BRIDGE_R0603-0R 49.291,56.354 r0 bottom
SB90 "SB_ON" SOLDER-BRIDGE_R0603-0R 39.066,57.204 r270 bottom
SB91 "SB_ON" SOLDER-BRIDGE_R0603-0R 37.191,55.229 r270 bottom
SB92 "SB_ON" SOLDER-BRIDGE_R0603-0R 34.641,54.629 r270 bottom
SB93 "SB_ON" SOLDER-BRIDGE_R0603-0R 49.291,54.929 r0 bottom
SB94 "SB_ON" SOLDER-BRIDGE_R0603-0R 49.291,53.154 r0 bottom
SB95 "SB_ON" SOLDER-BRIDGE_R0603-0R 20.391,51.434 r90 bottom
SB96 "SB_ON" SOLDER-BRIDGE_R0603-0R 49.291,51.804 r180 bottom
SB97 "SB_ON" SOLDER-BRIDGE_R0603-0R 23.725,49.75 r90 bottom
SB98 "SB_ON" SOLDER-BRIDGE_R0603-0R 32.691,38.879 r0 bottom
SB99 "SB_ON" SOLDER-BRIDGE_R0603-0R 28.646,21.589 r270 bottom
SB100 "SB_ON" SOLDER-BRIDGE_R0603-0R 59.975,17.125 r90 bottom
SB101 "SB_ON" SOLDER-BRIDGE_R0603-0R 34.075,6.675 r180 bottom
SB102 "SB_ON" SOLDER-BRIDGE_R0603-0R 54.95,6.675 r0 bottom
SB103 "SB_ON" SOLDER-BRIDGE_R0603-0R 45.725,85.575 r270 bottom
SB104 "SB_ON" SOLDER-BRIDGE_R0603-0R 51.725,41.85 r270 bottom
T1 "9013-SOT23" NPN_SOT23 29.391,6.954 r270 top
TP1 "Test Point" TP_SMD_1MM 53.891,109.754 r270 top
TP2 "Test Point" TP_SMD_1MM 26.041,94.004 r180 top
TP3 "Test Point" TP_SMD_1MM 17.241,93.979 r270 top
TP4 "Test Point" TP_SMD_1MM 32.016,84.729 r0 top
U1 "SN74LVC2T45DCUT" ICC_VSSOP8_DCU_R-PDSO-G8_2X2P30_P050 9.866,129.729 r180 top
U2 "STMPS2151STR" MOS_SOT23-5L 39.916,129.114 r180 top
U3 "ESD-TRANSIL" ESD_ST0201 21.541,128.679 r0 top value=ESDALC6V1-1U2
U4 "ESD-TRANSIL" ESD_ST0201 22.991,128.679 r180 top value=ESDALC6V1-1U2
U5 "ECMF02-2AMX6" ESD_QFN-6L_1P7X1P5_P050 49.541,126.504 r0 top
U6 "ESD-TRANSIL" ESD_QFN2_1P6X1_P125 52.024,126.293 r0 top value=ESDA7P60-1U1M
U7 "ST-LINKV3E_SWD" ICC_UFBGA201_176+25_10X10_P065 29.066,119.904 r90 top
U8 "ESDALC6V1W5" ESD_SOT323-5L 14.616,120.654 r270 top
U9 "LD3985M33R" REG_SOT23-5L 45.291,117.829 r90 top
U10 "SN74LVC2T45DCUT" ICC_VSSOP8_DCU_R-PDSO-G8_2X2P30_P050 15.866,116.429 r90 top
U11 "ST1L05CPU33R" ICC_DFN6-EPAD_3X3_P095 59.348,109.376 r180 top value="ST1L05CPU33R 3.3V 1.3A"
U12 "LD1117S50TR" REG_SOT223-TAB 21.441,104.054 r270 top
U13 "ST1L05BPUR" ICC_DFN6-EPAD_3X3_P095 20.666,94.929 r270 top
U14 "STM32H7_LQFP144_SMPS" ICC_LQFP144_20X20_P050_SOCKET_YAMAICHI_IC149-144-145-B5_NM 35.116,71.304 r90 top locked value=STM32H7A3ZIT6Q
U15 "LAN8742A-CZ-TR" ICC_VQFN24-EPAD_4X4_P050 37.691,38.629 r180 top
U16 "USBLC6-4SC6" ESD_SOT23-6L 37.691,32.279 r180 top
U17 "KMS-1102NL" TRS_DGKYD_KMS-1102NL 41.346,22.859 r180 top
U18 "STMPS2141STR" MOS_SOT23-5L 28.691,12.124 r0 top
U19 "USBLC6-2SC6" ESD_SOT23-6L 21.166,8.279 r180 top locked
U20 "ESD-TRANSIL" ESD_ST0201 55.748,8.523 r270 top value=ESDALC6V1-1U2
U21 "ESD-TRANSIL" ESD_QFN2_1P6X1_P125 24.866,6.129 r0 top value=ESDA7P60-1U1M
U22 "ESD-TRANSIL" ESD_ST0201 18.616,5.879 r180 top value=ESDALC6V1-1U2
U23 "ESD-TRANSIL" ESD_ST0201 14.566,3.704 r270 top value=ESDALC6V1-1U2
U24 "ESDALC6V1W5" ESD_SOT323-5L 8.991,115.354 r180 bottom
X1 "OSCILLATOR_4_PINS" OSC_NDK_NZ2520SB_4P 29.041,110.904 r90 top value=25MHz
X2 "XTAL_4_PINS" CRY_NX2016SA_4P 37.966,54.529 r0 top value="NX2016SA 25MHz"
X3 "XTAL_2_PINS" CRY_NX3215SA_2P 29.291,50.932 r180 top value=NX3215SA-32.768K
X4 "XTAL_4_PINS" CRY_NX2016SA_4P 43.666,39.379 r90 top value="NX2016SA 25MHz"

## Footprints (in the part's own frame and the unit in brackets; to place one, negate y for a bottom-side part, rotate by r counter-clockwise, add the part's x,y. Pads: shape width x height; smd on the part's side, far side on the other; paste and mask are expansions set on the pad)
C0402 [mm]
  rect 0.51x0.56 smd mask+0.05: 1(-0.45,0) 2(0.45,0)
  silkscreen extent -0.72,-0.35 0.72,0.35, body extent -0.5,-0.3 0.5,0.3, height 0.4
C0603 [mm]
  rect 0.64x0.89 smd mask+0.05: 1(-0.7,0) 2(0.7,0)
  silkscreen extent -1.05,-0.55 1.02,0.55, body extent -0.9,-0.5 0.9,0.5, height 1.4
C0805 [mm]
  rect 0.9x1.4 smd mask+0.05: 1(-0.85,0) 2(0.85,0)
  silkscreen extent -1.3,-0.77 1.3,0.77, body extent -1.1,-0.7 1.1,0.7, height 1.35
C1206_H1P6 [mm]
  rect 1.4x1.78 smd mask+0.05: 1(-1.4,0) 2(1.4,0)
  silkscreen extent -2.12,-0.97 2.15,0.97, body extent -1.7,-0.9 1.7,0.9, height 1.8
CON_RJ45_DGKYD_KRJ-CB4.2GYZNL [mm] "RJ45  connector, right angle"
  rect 1x1 hole 0.7 mask+0.05: 1(3.57,10.6)
  round 1 hole 0.7 mask+0.05: 2(2.55,11.7) 3(1.53,10.6) 4(0.51,11.7) 5(-0.51,10.6) 6(-1.53,11.7) 7(-2.55,10.6) 8(-3.57,11.7) 9(7.06,9.52) 10(4.77,9.52) 11(-4.77,9.52) 12(-7.06,9.52)
  oval 1.3x2.8 hole 0.7 slot 2.2 at 90 deg mask+0.05: SH1(8.04,4.2) SH2(-8.04,4.2)
  Multi-Layer keep-out lines w0.1: -9,0 -7,0 -7,6.4 cw(c-7,7.3) -7,8.2 7,8.2 cw(c7,7.3) 7,6.4 7,0 9,0
  silkscreen extent -8.23,-4.1 8.22,11.45, body extent -8.39,-4.1 8.39,11.9, height 6.85
CON_SAMTEC_SSW-108-23-X-D_N144_ARD [mm] "NUCLEO144_ARDUINO CONNECTOR"
  rect 1.85x1.85 / inner round 1.85 / far side rect 1.85x1.85 hole 1.1 mask+0.05: 1(8.89,1.27)
  round 1.85 hole 1.1 mask+0.05: 2(8.89,-1.27) 3(6.35,1.27) 4(6.35,-1.27) 5(3.81,1.27) 6(3.81,-1.27) 7(1.27,1.27) 8(1.27,-1.27) 9(-1.27,1.27) 10(-1.27,-1.27) 11(-3.81,1.27) 12(-3.81,-1.27) 13(-6.35,1.27) 14(-6.35,-1.27) 15(-8.89,1.27) 16(-8.89,-1.27)
  silkscreen extent -10.42,-2.47 10.42,2.47, body extent -10.42,-2.48 10.42,2.48, height 8.51
CON_SAMTEC_SSW-110-23-X-D_N144_ARD [mm] "NUCLEO144_ARDUINO CONNECTOR"
  rect 1.85x1.85 / inner round 1.85 / far side rect 1.85x1.85 hole 1.1 mask+0.05: 1(11.43,1.27)
  round 1.85 hole 1.1 mask+0.05: 2(11.43,-1.27) 3(8.89,1.27) 4(8.89,-1.27) 5(6.35,1.27) 6(6.35,-1.27) 7(3.81,1.27) 8(3.81,-1.27) 9(1.27,1.27) 10(1.27,-1.27) 11(-1.27,1.27) 12(-1.27,-1.27) 13(-3.81,1.27) 14(-3.81,-1.27) 15(-6.35,1.27) 16(-6.35,-1.27) 17(-8.89,1.27) 18(-8.89,-1.27) 19(-11.43,1.27) 20(-11.43,-1.27)
  silkscreen extent -12.96,-2.47 12.96,2.47, body extent -12.96,-2.48 12.96,2.48, height 8.51
CON_SAMTEC_SSW-115-23-X-D_N144_ARD [mm] "NUCLEO144_ARDUINO CONNECTOR"
  rect 1.85x1.85 / inner round 1.85 / far side rect 1.85x1.85 hole 1.1 mask+0.05: 1(17.78,1.27)
  round 1.85 hole 1.1 mask+0.05: 2(17.78,-1.27) 3(15.24,1.27) 4(15.24,-1.27) 5(12.7,1.27) 6(12.7,-1.27) 7(10.16,1.27) 8(10.16,-1.27) 9(7.62,1.27) 10(7.62,-1.27) 11(5.08,1.27) 12(5.08,-1.27) 13(2.54,1.27) 14(2.54,-1.27) 15(0,1.27) 16(0,-1.27) 17(-2.54,1.27) 18(-2.54,-1.27) 19(-5.08,1.27) 20(-5.08,-1.27) 21(-7.62,1.27) 22(-7.62,-1.27) 23(-10.16,1.27) 24(-10.16,-1.27) 25(-12.7,1.27) 26(-12.7,-1.27) 27(-15.24,1.27) 28(-15.24,-1.27) 29(-17.78,1.27) 30(-17.78,-1.27)
  silkscreen extent -19.31,-2.47 19.31,2.47, body extent -19.31,-2.48 19.31,2.48, height 8.51
CON_SAMTEC_SSW-117-23-X-D_N144_ARD [mm] "NUCLEO144_ARDUINO CONNECTOR"
  rect 1.85x1.85 / inner round 1.85 / far side rect 1.85x1.85 hole 1.1 mask+0.05: 1(20.32,1.27)
  round 1.85 hole 1.1 mask+0.05: 2(20.32,-1.27) 3(17.78,1.27) 4(17.78,-1.27) 5(15.24,1.27) 6(15.24,-1.27) 7(12.7,1.27) 8(12.7,-1.27) 9(10.16,1.27) 10(10.16,-1.27) 11(7.62,1.27) 12(7.62,-1.27) 13(5.08,1.27) 14(5.08,-1.27) 15(2.54,1.27) 16(2.54,-1.27) 17(0,1.27) 18(0,-1.27) 19(-2.54,1.27) 20(-2.54,-1.27) 21(-5.08,1.27) 22(-5.08,-1.27) 23(-7.62,1.27) 24(-7.62,-1.27) 25(-10.16,1.27) 26(-10.16,-1.27) 27(-12.7,1.27) 28(-12.7,-1.27) 29(-15.24,1.27) 30(-15.24,-1.27) 31(-17.78,1.27) 32(-17.78,-1.27) 33(-20.32,1.27) 34(-20.32,-1.27)
  silkscreen extent -21.85,-2.47 21.85,2.47, body extent -21.85,-2.48 21.85,2.48, height 8.51
CON_SAMTEC_TSW-102-07-G-S [mm]
  rect 1.85x1.85 / inner round 1.85 / far side rect 1.85x1.85 hole 1 mask+0.05: 1(-1.27,0)
  round 1.85 hole 1 mask+0.05: 2(1.27,0)
  silkscreen extent -2.58,-1.3 2.58,1.3, body extent -2.67,-1.3 2.58,1.3, height 8.38
CON_SAMTEC_TSW-102-09-X-S [mm]
  rect 1.85x1.85 / inner round 1.85 / far side rect 1.85x1.85 hole 1 mask+0.05: 1(-1.27,0)
  round 1.85 hole 1 mask+0.05: 2(1.27,0)
  silkscreen extent -2.64,-1.37 2.64,1.37, body extent -2.67,-1.3 2.58,1.3, height 8.38
CON_SAMTEC_TSW-103-07-F-S [mm]
  rect 1.85x1.85 / inner round 1.85 / far side rect 1.85x1.85 hole 1 mask+0.05: 1(-2.54,0)
  round 1.85 hole 1 mask+0.05: 2(0,0) 3(2.54,0)
  silkscreen extent -3.85,-1.3 3.85,1.3, body extent -3.91,-1.37 3.91,1.37, height 8.38
CON_SAMTEC_TSW-104-07-G-S [mm]
  rect 1.85x1.85 / inner round 1.85 / far side rect 1.85x1.85 hole 1 mask+0.05: 1(-3.81,0)
  round 1.85 hole 1 mask+0.05: 2(-1.27,0) 3(1.27,0) 4(3.81,0)
  silkscreen extent -5.12,-1.3 5.12,1.3, body extent -5.21,-1.37 5.18,1.37, height 8.38
CON_SAMTEC_TSW-104-07-X-D [mm]
  rect 1.85x1.85 / inner round 1.85 / far side rect 1.85x1.85 hole 1 mask+0.05: 1(-3.81,-1.27)
  round 1.85 hole 1 mask+0.05: 2(-3.81,1.27) 3(-1.27,-1.27) 4(-1.27,1.27) 5(1.27,-1.27) 6(1.27,1.27) 7(3.81,-1.27) 8(3.81,1.27)
  silkscreen extent -5.08,-2.54 5.08,2.54, body extent -5.08,-2.54 5.08,2.54, height 8.38
CON_SAMTEC_TSW-135-07-X-D [mm]
  rect 1.85x1.85 / inner round 1.85 / far side rect 1.85x1.85 hole 1 mask+0.05: 1(-43.18,-1.27)
  round 1.85 hole 1 mask+0.05: 2(-43.18,1.27) 3(-40.64,-1.27) 4(-40.64,1.27) 5(-38.1,-1.27) 6(-38.1,1.27) 7(-35.56,-1.27) 8(-35.56,1.27) 9(-33.02,-1.27) 10(-33.02,1.27) 11(-30.48,-1.27) 12(-30.48,1.27) 13(-27.94,-1.27) 14(-27.94,1.27) 15(-25.4,-1.27) 16(-25.4,1.27) 17(-22.86,-1.27) 18(-22.86,1.27) 19(-20.32,-1.27) 20(-20.32,1.27) 21(-17.78,-1.27) 22(-17.78,1.27) 23(-15.24,-1.27) 24(-15.24,1.27) 25(-12.7,-1.27) 26(-12.7,1.27) 27(-10.16,-1.27) 28(-10.16,1.27) 29(-7.62,-1.27) 30(-7.62,1.27) 31(-5.08,-1.27) 32(-5.08,1.27) 33(-2.54,-1.27) 34(-2.54,1.27) 35(0,-1.27) 36(0,1.27) 37(2.54,-1.27) 38(2.54,1.27) 39(5.08,-1.27) 40(5.08,1.27) 41(7.62,-1.27) 42(7.62,1.27) 43(10.16,-1.27) 44(10.16,1.27) 45(12.7,-1.27) 46(12.7,1.27) 47(15.24,-1.27) 48(15.24,1.27) 49(17.78,-1.27) 50(17.78,1.27) 51(20.32,-1.27) 52(20.32,1.27) 53(22.86,-1.27) 54(22.86,1.27) 55(25.4,-1.27) 56(25.4,1.27) 57(27.94,-1.27) 58(27.94,1.27) 59(30.48,-1.27) 60(30.48,1.27) 61(33.02,-1.27) 62(33.02,1.27) 63(35.56,-1.27) 64(35.56,1.27) 65(38.1,-1.27) 66(38.1,1.27) 67(40.64,-1.27) 68(40.64,1.27) 69(43.18,-1.27) 70(43.18,1.27)
  silkscreen extent -44.45,-2.54 44.45,2.54, body extent -44.45,-2.54 44.45,2.54, height 8.38
CON_STDC14_Receiver_MEDIUM_WITH_MIPI10_3D [mm] "compatible with FTSH-105-01-L-DV,-K and FTSH-107-01-L-DV,-K,-A,-P,-ES"
  round 0 hole 1.19 unplated mask+0.05: 0(-5.445,0) 0(5.445,0)
  round 0 hole 0.97 unplated mask+0.05: 0(-3.175,0) 0(3.175,0)
  rect 0.74x2.79 smd mask+0.05: 1(-3.81,-2.032) 2(-3.81,2.032) 3(-2.54,-2.032) 4(-2.54,2.032) 5(-1.27,-2.032) 6(-1.27,2.032) 7(0,-2.032) 8(0,2.032) 9(1.27,-2.032) 10(1.27,2.032) 11(2.54,-2.032) 12(2.54,2.032) 13(3.81,-2.032) 14(3.81,2.032)
  silkscreen extent -6.3,-4.38 6.3,3.6, body extent -6.3,-2.92 6.3,2.92, height 6.6
CON_USBMICROAB_MOLEX_47590-0001_H3 [mm]
  rect 0.4x1.35 smd mask+0.05: 1(1.3,4.125) 2(0.65,4.125) 3(0,4.125) 4(-0.65,4.125) 5(-1.3,4.125)
  oval 1.05x1.25 hole 0.65 slot 0.85 at 90 deg mask+0.05: 6(-2.225,4.45) 7(2.225,4.45)
  rrect50% 1.375x1.9 hole 0.6 slot 1.3 at 90 deg copper offset 0.188,0 mask+0.05: 8(-4.175,1.45)
  rrect50% 1.375x1.9 hole 0.6 slot 1.3 at 90 deg copper offset -0.188,0 mask+0.05: 9(4.175,1.45)
  rect 2.9x1.9 smd mask+0.05: 10(0,1.45)
  oval 0.85x2.425 hole 0.85 slot 2.425 at 90 deg unplated mask+0.1: 11(-2.375,0.8) 12(2.375,0.8)
  silkscreen extent -4.1,-1.3 4.1,4.3, body extent -4.32,-1.36 4.33,4.6, height 3
CON_USBMICROB_MOLEX_105017-0001_H2P90 [mm]
  rect 0.4x1.35 smd mask+0.05: 1(-1.3,4.15) 2(-0.65,4.15) 3(0,4.15) 4(0.65,4.15) 5(1.3,4.15)
  round 1.5 hole 0.9 mask+0.05: 6(-2.5,4.15) 7(2.5,4.15)
  oval 1.2x1.9 hole 0.6 slot 1.3 at 90 deg mask+0.05: 8(3.5,1.45) 9(-3.5,1.45)
  rect 1.5x1.9 smd mask+0.05: 10(-1,1.45) 11(1,1.45)
  Top Layer region: -3.5,2.4 -2.3,2.4 -2.3,0.5 -3.5,0.5 -3.5,2.4
  Top Layer region: 2.3,2.4 3.5,2.4 3.5,0.5 2.3,0.5 2.3,2.4
  silkscreen extent -4,-0.7 4,4.6, body extent -4.1,-1.15 4.1,4.66, height 2.9
CRY_NX2016SA_4P [mm]
  rect 0.85x0.75 smd mask+0.05: 1(-0.675,-0.525) 2(0.675,-0.525) 3(0.675,0.525) 4(-0.675,0.525)
  silkscreen extent -1.22,-1.02 1.05,0.85, body extent -1.05,-0.85 1.05,0.85, height 0.7
CRY_NX3215SA_2P [mm]
  rect 1x1.8 smd mask+0.05: 1(-1.25,0) 2(1.25,0)
  silkscreen extent -0.63,-0.8 0.63,0.8, body extent -1.65,-0.8 1.65,0.8, height 0.9
DIO_SOD323 [mm]
  rect 1.06x0.54 smd mask+0.05: 1(-1.07,0) 2(1.07,0)
  silkscreen extent -0.9,-0.72 0.9,0.72, body extent -1.3,-0.78 1.3,0.78, height 1.17
ESD_QFN2_1P6X1_P125 [mm]
  rect 0.55x0.8 smd mask+0.05: 1(-0.625,0) 2(0.625,0)
  silkscreen extent -1,-0.55 0.85,0.55, body extent -0.85,-0.55 0.85,0.55, height 0.61
ESD_QFN-6L_1P7X1P5_P050 [mm]
  rect 0.25x0.6 smd mask+0.05: 1(-0.5,-0.65) 2(0,-0.65) 3(0.5,-0.65) 4(0.5,0.65) 5(0,0.65) 6(-0.5,0.65)
  silkscreen extent -0.9,-0.8 0.9,0.8, body extent -0.9,-0.8 0.9,0.8, height 0.56
ESD_SOT23-6L [mm]
  rect 0.6x1.2 smd mask+0.05: 1(-0.95,-1.15) 2(0,-1.15) 3(0.95,-1.15) 4(0.95,1.15) 5(0,1.15) 6(-0.95,1.15)
  silkscreen extent -1.53,-0.87 1.53,0.87, body extent -1.52,-1.5 1.52,1.5, height 1.45
ESD_SOT323-5L [mm]
  rect 0.4x1.2 smd mask+0.05: 1(-0.65,-0.85) 2(0,-0.85) 3(0.65,-0.85) 4(0.65,0.85) 5(-0.65,0.85)
  silkscreen extent -1.22,-1.21 1.22,0.77, body extent -1.15,-1.05 1.15,1.05, height 1.1
ESD_ST0201 [mm]
  rect 0.425x0.33 smd mask+0.05: 1(-0.312,0) 2(0.312,0)
  silkscreen extent -0.55,-0.3 0.33,0.3, body extent -0.34,-0.18 0.34,0.18, height 0.34
ICC_DFN6-EPAD_3X3_P095 [mm]
  rect 0.45x0.5 smd mask+0.05: 1(-0.95,-1.3) 2(0,-1.3) 3(0.95,-1.3) 4(0.95,1.3) 5(0,1.3) 6(-0.95,1.3)
  rect 2.5x1.7 smd mask+0.05: EP(0,0)
  silkscreen extent -1.55,-1.55 1.55,1.55, body extent -1.55,-1.55 1.55,1.55, height 1
ICC_LQFP144_20X20_P050_SOCKET_YAMAICHI_IC149-144-145-B5_NM [mm]
  rect 1x2.5 smd rot 45 mask+0.05: 0(-10.96,-10.96) 0(10.96,10.96)
  rect 1x2.5 smd rot 135 mask+0.05: 0(-10.96,10.96) 0(10.96,-10.96)
  round 0 hole 1.5 unplated mask+0.05: 0(0,8) 0(0,-8)
  rect 1.65x0.5 smd mask+0.05: 1(-10.825,8.85) 36(-10.825,-8.85) 73(10.825,-8.85) 108(10.825,8.85)
  rect 1.65x0.3 smd mask+0.05: 2(-10.825,8.25) 3(-10.825,7.75) 4(-10.825,7.25) 5(-10.825,6.75) 6(-10.825,6.25) 7(-10.825,5.75) 8(-10.825,5.25) 9(-10.825,4.75) 10(-10.825,4.25) 11(-10.825,3.75) 12(-10.825,3.25) 13(-10.825,2.75) 14(-10.825,2.25) 15(-10.825,1.75) 16(-10.825,1.25) 17(-10.825,0.75) 18(-10.825,0.25) 19(-10.825,-0.25) 20(-10.825,-0.75) 21(-10.825,-1.25) 22(-10.825,-1.75) 23(-10.825,-2.25) 24(-10.825,-2.75) 25(-10.825,-3.25) 26(-10.825,-3.75) 27(-10.825,-4.25) 28(-10.825,-4.75) 29(-10.825,-5.25) 30(-10.825,-5.75) 31(-10.825,-6.25) 32(-10.825,-6.75) 33(-10.825,-7.25) 34(-10.825,-7.75) 35(-10.825,-8.25) 74(10.825,-8.25) 75(10.825,-7.75) 76(10.825,-7.25) 77(10.825,-6.75) 78(10.825,-6.25) 79(10.825,-5.75) 80(10.825,-5.25) 81(10.825,-4.75) 82(10.825,-4.25) 83(10.825,-3.75) 84(10.825,-3.25) 85(10.825,-2.75) 86(10.825,-2.25) 87(10.825,-1.75) 88(10.825,-1.25) 89(10.825,-0.75) 90(10.825,-0.25) 91(10.825,0.25) 92(10.825,0.75) 93(10.825,1.25) 94(10.825,1.75) 95(10.825,2.25) 96(10.825,2.75) 97(10.825,3.25) 98(10.825,3.75) 99(10.825,4.25) 100(10.825,4.75) 101(10.825,5.25) 102(10.825,5.75) 103(10.825,6.25) 104(10.825,6.75) 105(10.825,7.25) 106(10.825,7.75) 107(10.825,8.25)
  rect 0.5x1.65 smd mask+0.05: 37(-8.85,-10.825) 72(8.85,-10.825) 109(8.85,10.825) 144(-8.85,10.825)
  rect 0.3x1.65 smd mask+0.05: 38(-8.25,-10.825) 39(-7.75,-10.825) 40(-7.25,-10.825) 41(-6.75,-10.825) 42(-6.25,-10.825) 43(-5.75,-10.825) 44(-5.25,-10.825) 45(-4.75,-10.825) 46(-4.25,-10.825) 47(-3.75,-10.825) 48(-3.25,-10.825) 49(-2.75,-10.825) 50(-2.25,-10.825) 51(-1.75,-10.825) 52(-1.25,-10.825) 53(-0.75,-10.825) 54(-0.25,-10.825) 55(0.25,-10.825) 56(0.75,-10.825) 57(1.25,-10.825) 58(1.75,-10.825) 59(2.25,-10.825) 60(2.75,-10.825) 61(3.25,-10.825) 62(3.75,-10.825) 63(4.25,-10.825) 64(4.75,-10.825) 65(5.25,-10.825) 66(5.75,-10.825) 67(6.25,-10.825) 68(6.75,-10.825) 69(7.25,-10.825) 70(7.75,-10.825) 71(8.25,-10.825) 110(8.25,10.825) 111(7.75,10.825) 112(7.25,10.825) 113(6.75,10.825) 114(6.25,10.825) 115(5.75,10.825) 116(5.25,10.825) 117(4.75,10.825) 118(4.25,10.825) 119(3.75,10.825) 120(3.25,10.825) 121(2.75,10.825) 122(2.25,10.825) 123(1.75,10.825) 124(1.25,10.825) 125(0.75,10.825) 126(0.25,10.825) 127(-0.25,10.825) 128(-0.75,10.825) 129(-1.25,10.825) 130(-1.75,10.825) 131(-2.25,10.825) 132(-2.75,10.825) 133(-3.25,10.825) 134(-3.75,10.825) 135(-4.25,10.825) 136(-4.75,10.825) 137(-5.25,10.825) 138(-5.75,10.825) 139(-6.25,10.825) 140(-6.75,10.825) 141(-7.25,10.825) 142(-7.75,10.825) 143(-8.25,10.825)
  silkscreen extent -10.1,-10.1 10.1,10.1, body extent -11,-11 11,11, height 1.6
